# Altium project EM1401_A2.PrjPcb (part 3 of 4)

## Sheet uController.SchDoc: Microcontroller
size B; Date: Not shown in title block; ApprovedBy: Not shown in title block; CheckedBy: Not shown in title block; Author: Not shown in title block; CompanyName: Not shown in title block; DrawnBy: Not shown in title block; Engineer: Not shown in title block; Organization: Not shown in title block; Address1: Not shown in title block; Address2: Not shown in title block; Address3: Not shown in title block; Address4: Not shown in title block; DocumentNumber: 9; Revision: Use project parameter SCH_Rev; SheetNumber: 10; SheetTotal: 14; PageSetup: Record=PageOptions|CenterHorizontal=True|CenterVertical=True|PrintScale=1.09|XCorrection=1.00|YCorrection=1.00|PrintKind=0|BorderSize=5000000|LeftOffset=0|BottomOffset=0|Orientation=2|PaperLength=1000|PaperWidth=1000|Scale=100|PaperSource=15|PrintQuality=600|MediaType=1|DitherType=10|PaperKind=11x17|PrintScaleMode=1
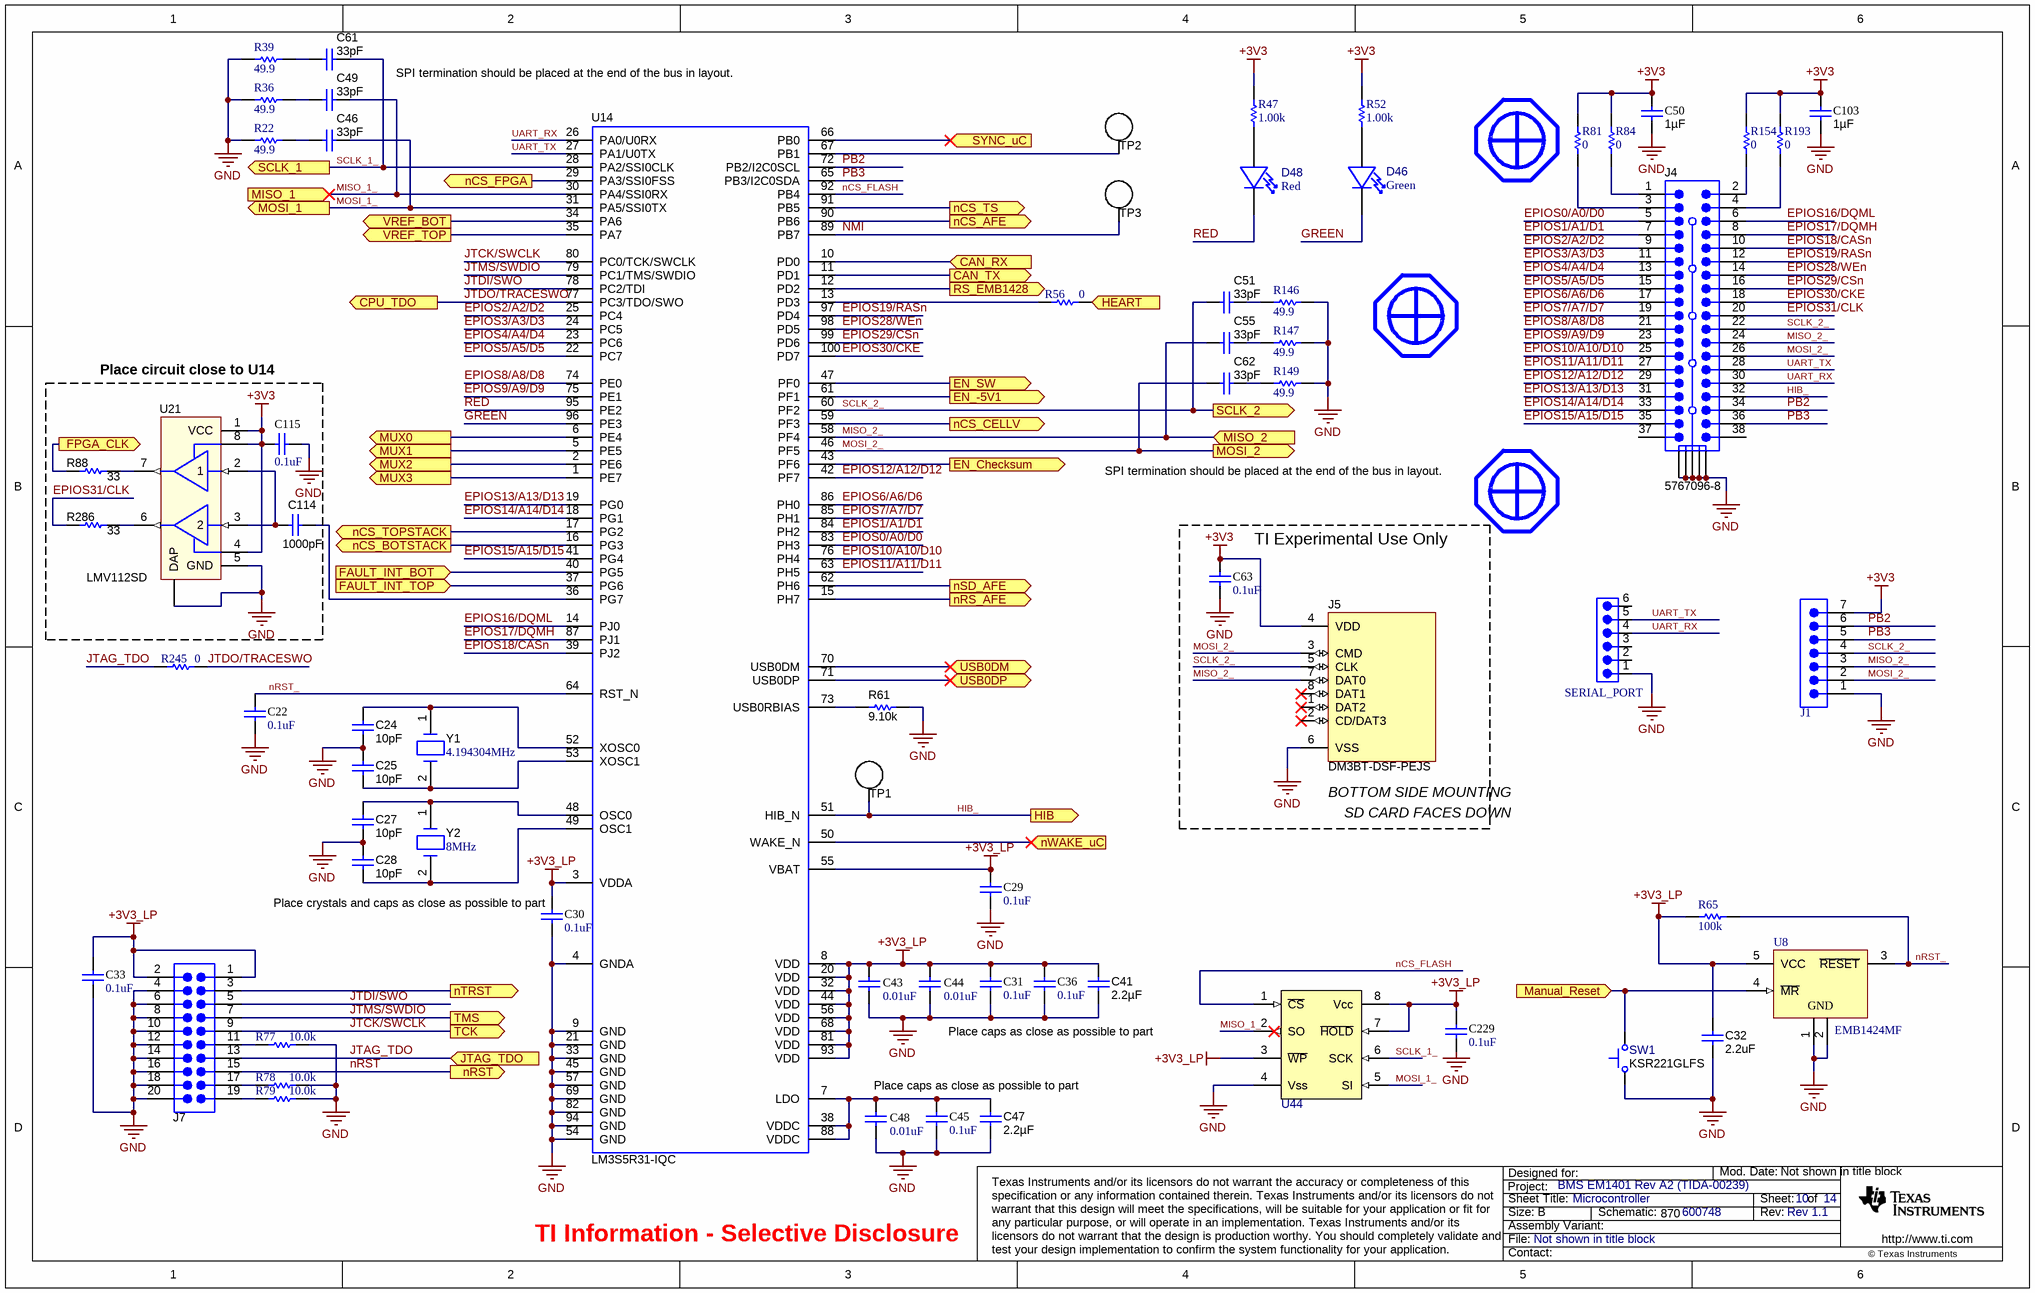
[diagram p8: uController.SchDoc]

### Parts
C22  value 0.1uF  [0603L]  (hidden comment: C1608X7R1C104K)
C24  ValueDisplayed: 10pF  [0603L]  (hidden comment: C1608C0G1H100D)
C25  ValueDisplayed: 10pF  [0603L]  (hidden comment: C1608C0G1H100D)
C27  ValueDisplayed: 10pF  [0603L]  (hidden comment: C1608C0G1H100D)
C28  ValueDisplayed: 10pF  [0603L]  (hidden comment: C1608C0G1H100D)
C29  value 0.1uF  [0603L]  (hidden comment: C1608X7R1C104K)
C30  value 0.1uF  [0603L]  (hidden comment: C1608X7R1C104K)
C31  value 0.1uF  [0603L]  (hidden comment: C1608X7R1C104K)
C32  value 2.2uF  [0805_HV]  (hidden comment: C2012X7R1C225K)
C33  value 0.1uF  [0603L]  (hidden comment: C1608X7R1C104K)
C36  value 0.1uF  [0603L]  (hidden comment: C1608X7R1C104K)
C41  ValueDisplayed: 2.2µF  [1210]  (hidden comment: GRM31MR71E225KA93L)
C43  value 0.01uF  [0603L]  (hidden comment: GRM188R71E103KA01D)
C44  value 0.01uF  [0603L]  (hidden comment: GRM188R71E103KA01D)
C45  value 0.1uF  [0603L]  (hidden comment: C1608X7R1C104K)
C46  value 33pF  [0603L]  (hidden comment: C1608C0G1H330J)
C47  ValueDisplayed: 2.2µF  [1210]  (hidden comment: GRM31MR71E225KA93L)
C48  value 0.01uF  [0603L]  (hidden comment: GRM188R71E103KA01D)
C49  value 33pF  [0603L]  (hidden comment: C1608C0G1H330J)
C50  ValueDisplayed: 1µF  [0603L]  (hidden comment: C1608X7R1C105K)
C51  value 33pF  [0603L]  (hidden comment: C1608C0G1H330J)
C55  value 33pF  [0603L]  (hidden comment: C1608C0G1H330J)
C61  value 33pF  [0603L]  (hidden comment: C1608C0G1H330J)
C62  value 33pF  [0603L]  (hidden comment: C1608C0G1H330J)
C63  value 0.1uF  [0603L]  (hidden comment: C1608X7R1C104K)
C103  ValueDisplayed: 1µF  [0603L]  (hidden comment: C1608X7R1C105K)
C114  ValueDisplayed: 1000pF  [0603L]  (hidden comment: GRM188R71C102KA01D)
C115  value 0.1uF  [0603L]  (hidden comment: C1608X7R1C104K)
C229  value 0.1uF  [0603L]  (hidden comment: C1608X7R1C104K)
D46  value Green  [HSMG-xxx]  (hidden comment: HSMG-C150)
D48  value Red  [HSMH-xxx]  (hidden comment: HSMH-C150)
J1  TSW-107-07-G-S  [TSW-107-XX-XXX-S]  (value not drawn)
J4  5767096-8
J5  DM3BT-DSF-PEJS  [DM3BT-DSF-PEJS]
J7  AWHW20-G-SMD-R  [2X10 Shrouded Surface Mount HDR]  (value not drawn)
MNT6  Used in BOM report  [4-40 screw]  (value not drawn)
MNT7  Used in BOM report  [4-40 screw]  (value not drawn)
MNT8  Used in BOM report  [4-40 screw]  (value not drawn)
R22  value 49.9  [0603L]  (hidden comment: CRCW060349R9FKEA)
R36  value 49.9  [0603L]  (hidden comment: CRCW060349R9FKEA)
R39  value 49.9  [0603L]  (hidden comment: CRCW060349R9FKEA)
R47  value 1.00k  [0603L]  (hidden comment: CRCW06031K00FKEA)
R52  value 1.00k  [0603L]  (hidden comment: CRCW06031K00FKEA)
R56  value 0  [0603L]  (hidden comment: CRCW06030000Z0EA)
R61  value 9.10k  [0603L]  (hidden comment: RC0603FR-079K1L)
R65  value 100k  [0603L]  (hidden comment: CRCW0603100KFKEA)
R77  value 10.0k  [0603L]  (hidden comment: CRCW060310K0FKEA)
R78  value 10.0k  [0603L]  (hidden comment: CRCW060310K0FKEA)
R79  value 10.0k  [0603L]  (hidden comment: CRCW060310K0FKEA)
R81  value 0  [0603L]  (hidden comment: CRCW06030000Z0EA)
R84  value 0  [0603L]  (hidden comment: CRCW06030000Z0EA)
R88  value 33  [0603L]  (hidden comment: CRCW060333R0JNEA)
R146  value 49.9  [0603L]  (hidden comment: CRCW060349R9FKEA)
R147  value 49.9  [0603L]  (hidden comment: CRCW060349R9FKEA)
R149  value 49.9  [0603L]  (hidden comment: CRCW060349R9FKEA)
R154  value 0  [0603L]  (hidden comment: CRCW06030000Z0EA)
R193  value 0  [0603L]  (hidden comment: CRCW06030000Z0EA)
R245  value 0  [0603L]  (hidden comment: CRCW06030000Z0EA)
R286  value 33  [0603L]  (hidden comment: CRCW060333R0JNEA)
SERIAL_PORT  961106-6404-AR  [1X6 100MIL PITCH]  (value not drawn)
SW1  KSR221GLFS  [KSR]
TP1  TESTPOINT  [TESTPOINT]  (value not drawn)  (no BOM)
TP2  TESTPOINT  [TESTPOINT]  (value not drawn)  (no BOM)
TP3  TESTPOINT  [TESTPOINT]  (value not drawn)  (no BOM)
U8  EMB1424MF  [MF05A_N]
U14  LM3S5R31-IQC  [QFP50P1600X1600X160-100N]
U21  LMV112SD  [SDA08A]
U44  25LC512T-I/SN  [M08A_L]  (value not drawn)
Y1  value 4.194304MHz  [HC-49US crystal]  (hidden comment: ABLSG-4.194304MHZ-D-2-Y-T)
Y2  value 8MHz  [HC-49US crystal]  (hidden comment: ABLS2-8.000MHZ-D4Y-T)

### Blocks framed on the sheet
Place circuit close to U14: C114 C115 R88 R286 U21
TI Experimental Use Only: C63 J5

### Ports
CAN_RX (in), CAN_TX (out), CPU_TDO (out), EN_-5V1 (out), EN_Checksum (out), EN_SW (out), FAULT_INT_BOT (in), FAULT_INT_TOP (in), FPGA_CLK (out), HEART (in), HIB (out), JTAG_TDO (in), Manual_Reset (in), MISO_1 (in), MISO_2 (in), MOSI_1 (out), MOSI_2 (out), MUX0 (out), MUX1 (out), MUX2 (out), MUX3 (out), nCS_AFE (out), nCS_BOTSTACK (out), nCS_CELLV (out), nCS_FPGA (out), nCS_TOPSTACK (out), nCS_TS (out), nRS_AFE (out), nRST (out), nSD_AFE (out), nTRST (out), nWAKE_uC (in), RS_EMB1428 (out), SCLK_1 (out), SCLK_2 (out), SYNC_uC (in), TCK (out), TMS (out), USB0DM (bidir), USB0DP (bidir), VREF_BOT (out), VREF_TOP (out)

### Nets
+3V3: C50.2 C63.1 C103.2 C115.2 J1.7 J5.4(VDD) R47.2 R52.2 R81.1 R84.1 R154.1 R193.1 U21.1(VCC) U21.4(EN2) U21.8(EN1)
+3V3_LP: C29.1 C30.1 C31.1 C32.1 C33.2 C36.1 C41.1 C43.2 C44.2 C229.2 J7.1 J7.2 R65.1 U8.5(VCC) U14.3(VDDA) U14.8(VDD) U14.20(VDD) U14.32(VDD) U14.44(VDD) U14.55(VBAT) U14.56(VDD) U14.68(VDD) U14.81(VDD) U14.93(VDD) U44.3(~{WP}) U44.7(~{HOLD}) U44.8(Vcc)
GND: C22.2 C24.2 C25.2 C27.2 C28.2 C29.2 C30.2 C31.2 C32.2 C33.1 C36.2 C41.2 C43.1 C44.1 C45.2 C47.2 C48.1 C50.1 C63.2 C103.1 C115.1 C229.1 J1.1 J4.39 J4.40 J4.41 J4.42 J4.43 J5.6(VSS) J7.4 J7.6 J7.8 J7.10 J7.12 J7.14 J7.16 J7.18 J7.20 R22.2 R36.2 R39.2 R61.2 R77.1 R78.1 R79.1 R146.1 R147.1 R149.1 SERIAL_PORT.1 SW1.1 U8.1(GND) U8.2(GND) U14.4(GNDA) U14.9(GND) U14.21(GND) U14.33(GND) U14.45(GND) U14.54(GND) U14.57(GND) U14.69(GND) U14.82(GND) U14.94(GND) U21.5(GND) U21.9(DAP) U44.4(Vss)  [project net BAT0]
EN_Checksum_: U14.43(PF6) ; port EN_Checksum
EN_SW_: U14.47(PF0) ; port EN_SW
EPIOS0/A0/D0: J4.5 U14.83(PH3)
EPIOS1/A1/D1: J4.7 U14.84(PH2)
EPIOS2/A2/D2: J4.9 U14.25(PC4)
EPIOS3/A3/D3: J4.11 U14.24(PC5)
EPIOS4/A4/D4: J4.13 U14.23(PC6)
EPIOS5/A5/D5: J4.15 U14.22(PC7)
EPIOS6/A6/D6: J4.17 U14.86(PH0)
EPIOS7/A7/D7: J4.19 U14.85(PH1)
EPIOS8/A8/D8: J4.21 U14.74(PE0)
EPIOS9/A9/D9: J4.23 U14.75(PE1)
EPIOS10/A10/D10: J4.25 U14.76(PH4)
EPIOS11/A11/D11: J4.27 U14.63(PH5)
EPIOS12/A12/D12: J4.29 U14.42(PF7)
EPIOS13/A13/D13: J4.31 U14.19(PG0)
EPIOS14/A14/D14: J4.33 U14.18(PG1)
EPIOS15/A15/D15: J4.35 U14.41(PG4)
EPIOS16/DQML: J4.6 U14.14(PJ0)
EPIOS17/DQMH: J4.8 U14.87(PJ1)
EPIOS18/CASn: J4.10 U14.39(PJ2)
EPIOS19/RASn: J4.12 U14.97(PD4)
EPIOS28/WEn: J4.14 U14.98(PD5)
EPIOS29/CSn: J4.16 U14.99(PD6)
EPIOS30/CKE: J4.18 U14.100(PD7)
EPIOS31/CLK: J4.20 R286.1
FAULT_INT_BOT_: U14.40(PG5) ; port FAULT_INT_BOT
FAULT_INT_TOP_: U14.37(PG6) ; port FAULT_INT_TOP
FPGA_CLK_: R88.1 ; port FPGA_CLK
GREEN: D46.2(Cathode) U14.96(PE3)
HEART_: R56.1 ; port HEART
HIB_: J4.32 TP1.1 U14.51(HIB_N) ; port HIB
JTAG_TDO: J7.13 R245.2 ; port JTAG_TDO
JTCK/SWCLK: J7.9 U14.80(PC0/TCK/SWCLK) ; port TCK
JTDI/SWO: J7.5 U14.78(PC2/TDI)
JTDO/TRACESWO: R245.1 U14.77(PC3/TDO/SWO) ; port CPU_TDO
JTMS/SWDIO: J7.7 U14.79(PC1/TMS/SWDIO) ; port TMS
Manual_Reset_: SW1.2 U8.4(~{MR}) ; port Manual_Reset
MISO_1_: C49.2 U14.30(PA4/SSI0RX) U44.2(SO) ; port MISO_1
MISO_2_: C55.1 J1.3 J4.24 J5.7(DAT0) U14.58(PF4) ; port MISO_2
MOSI_1_: C46.2 U14.31(PA5/SSI0TX) U44.5(SI) ; port MOSI_1
MOSI_2_: C62.1 J1.2 J4.26 J5.3(CMD) U14.46(PF5) ; port MOSI_2
MUX0_: U14.6(PE4) ; port MUX0
MUX1_: U14.5(PE5) ; port MUX1
MUX2_: U14.2(PE6) ; port MUX2
MUX3_: U14.1(PE7) ; port MUX3
nCS_AFE_: U14.90(PB6) ; port nCS_AFE
nCS_BOTSTACK_: U14.16(PG3) ; port nCS_BOTSTACK
nCS_CELLV_: U14.59(PF3) ; port nCS_CELLV
nCS_FLASH: U14.92(PB4) U44.1(~{CS})
nCS_FPGA_: U14.29(PA3/SSI0FSS) ; port nCS_FPGA
nCS_TOPSTACK_: U14.17(PG2) ; port nCS_TOPSTACK
nCS_TS_: U14.91(PB5) ; port nCS_TS
NMI: TP3.1 U14.89(PB7)
nRS_AFE_: U14.15(PH7) ; port nRS_AFE
nRST: J7.15 ; port nRST
nRST_: C22.1 R65.2 U8.3(~{RESET}) U14.64(RST_N)
nSD_AFE_: U14.62(PH6) ; port nSD_AFE
PB2: J1.6 J4.34 U14.72(PB2/I2C0SCL)
PB3: J1.5 J4.36 U14.65(PB3/I2C0SDA)
RED: D48.2(Cathode) U14.95(PE2)
RS_EMB1428_: U14.12(PD2) ; port RS_EMB1428
SCLK_1_: C61.2 U14.28(PA2/SSI0CLK) U44.6(SCK) ; port SCLK_1
SCLK_2_: C51.1 J1.4 J4.22 J5.5(CLK) U14.60(PF2) ; port SCLK_2
SYNC_: U14.66(PB0) ; port SYNC_uC
UART_RX: J4.30 SERIAL_PORT.4 U14.26(PA0/U0RX)
UART_TX: J4.28 SERIAL_PORT.5 U14.27(PA1/U0TX)
VREF_BOT_: U14.34(PA6) ; port VREF_BOT
VREF_TOP_: U14.35(PA7) ; port VREF_TOP
NetC24_1: C24.1 U14.52(XOSC0) Y1.1
NetC25_1: C25.1 U14.53(XOSC1) Y1.2
NetC27_1: C27.1 U14.48(OSC0) Y2.1
NetC28_1: C28.1 U14.49(OSC1) Y2.2
NetC45_1: C45.1 C47.1 C48.2 U14.7(LDO) U14.38(VDDC) U14.88(VDDC)
NetC46_1: C46.1 R22.1
NetC49_1: C49.1 R36.1
NetC51_2: C51.2 R146.2
NetC55_2: C55.2 R147.2
NetC61_1: C61.1 R39.1
NetC62_2: C62.2 R149.2
NetC114_1: C114.1 U14.36(PG7)
NetC114_2: C114.2 U21.2(IN1) U21.3(IN2)
NetD4_1: U14.70(USB0DM) ; port USB0DM
NetD9_1: U14.71(USB0DP) ; port USB0DP
NetD46_1: D46.1(Anode) R52.1
NetD48_1: D48.1(Anode) R47.1
NetJ4_1: J4.1 R84.2
NetJ4_2: J4.2 R154.2
NetJ4_3: J4.3 R81.2
NetJ4_4: J4.4 R193.2
NetJ7_3: J7.3 ; port nTRST
NetJ7_11: J7.11 R77.2
NetJ7_17: J7.17 R78.2
NetJ7_19: J7.19 R79.2
NetQ45_3: U14.50(WAKE_N) ; port nWAKE_uC
NetR27_1: U14.11(PD1) ; port CAN_TX
NetR38_1: U14.10(PD0) ; port CAN_RX
NetR56_2: R56.2 U14.13(PD3)
NetR61_1: R61.1 U14.73(USB0RBIAS)
NetR88_2: R88.2 U21.7(OUT1)
NetR94_2: U14.61(PF1) ; port EN_-5V1
NetR286_2: R286.2 U21.6(OUT2)
NetTP2_1: TP2.1 U14.67(PB1)

Not connected (* = marked no-connect by the designer): J4 37 38; J5 1(DAT2)* 2(CD/DAT3)* 8(DAT1)*; SERIAL_PORT 2 3 6

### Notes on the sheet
- SPI termination should be placed at the end of the bus in layout.
- (near MNT7) SPI termination should be placed at the end of the bus in layout.
- (near J5) BOTTOM SIDE MOUNTING
- SD CARD FACES DOWN
- (near C30) Place crystals and caps as close as possible to part
- Place caps as close as possible to part
- TI Information - Selective Disclosure

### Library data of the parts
C22 C29-C31 C33 C36 C45 C63 C115 C229 = C1608X7R1C104K: CAP, CERM, 0.1uF, 16V, +/-10%, X7R, 0603; Manufacturer: TDK; Cap_Case: 0603; ESR_Ohm: 0.017; Polarized: N; TaMax_C: 125; TaMin_C: -55; Tolerance_%: 10; VDC_V: 16; Cap_F: 0.0000001; CompType: Capacitor; Value1: 0.017 ohm; U/M: EA; ValueDisplayed: 0.1µF
C24 C25 C27 C28 = C1608C0G1H100D: CAP, CERM, 10pF, 50V, +/-5%, C0G/NP0, 0603; Manufacturer: TDK; Cap_Case: 0603; ESR_Ohm: 0.3492; Polarized: N; TaMax_C: 125; TaMin_C: -55; Tolerance_%: 5; VDC_V: 50; Cap_F: 0.00000000001; CompType: Capacitor; U/M: EA; Value1: 0.3492 ohm
C32 = C2012X7R1C225K: CAP, CERM, 2.2uF, 16V, +/-10%, X7R, 0805; Manufacturer: TDK; Cap_Case: 0805; ESR_Ohm: 0.0049; Polarized: N; TaMax_C: 125; TaMin_C: -55; Tolerance_%: 10; VDC_V: 16; Cap_F: 0.0000022; CompType: Capacitor; Value1: 0.0049 ohm; U/M: EA; ValueDisplayed: 2.2µF
C41 C47 = GRM31MR71E225KA93L: CAP, CERM, 2.2uF, 25V, +/-10%, X7R, 1206; Manufacturer: MuRata; Polarized: N; TaMax_C: 125; TaMin_C: -55; Tolerance_%: 10; VDC_V: 25; Cap_F: 0.0000022; CompType: Capacitor; U/M: EA
C43 C44 C48 = GRM188R71E103KA01D: CAP, CERM, 0.01uF, 25V, +/-10%, X7R, 0603; Manufacturer: MuRata; Cap_Case: 0603; Polarized: N; TaMax_C: 125; TaMin_C: -55; Tolerance_%: 10; VDC_V: 25; Cap_F: 0.00000001; CompType: Capacitor; U/M: EA; ValueDisplayed: 0.01µF
C46 C49 C51 C55 C61 C62 = C1608C0G1H330J: CAP, CERM, 33pF, 50V, +/-5%, C0G/NP0, 0603; Manufacturer: TDK; Cap_Case: 0603; ESR_Ohm: 0.2649; Polarized: N; TaMax_C: 125; TaMin_C: -55; Tolerance_%: 5; VDC_V: 50; Cap_F: 0.000000000033; CompType: Capacitor; Value1: 0.2649 ohm; U/M: EA
C50 C103 = C1608X7R1C105K: CAP, CERM, 1uF, 16V, +/-10%, X7R, 0603; Manufacturer: TDK; Cap_Case: 0603; ESR_Ohm: 0.0057; Polarized: N; TaMax_C: 125; TaMin_C: -55; Tolerance_%: 10; VDC_V: 16; Cap_F: 0.000001; CompType: Capacitor; Value1: 0.0057 ohm; U/M: EA
C114 = GRM188R71C102KA01D: CAP, CERM, 1000pF, 16V, +/-10%, X7R, 0603; Manufacturer: MuRata; Polarized: N; CompType: Capacitor; U/M: EA; Cap_F: 0.000000001; Tolerance_%: 10; VDC_V: 16; TaMin_C: -55; TaMax_C: 125; Cap_Case: 0603
D46 = HSMG-C150: LED 570NM GREEN DIFF 1206 SMD; Manufacturer: Avago Technologies; SymbolVersion: 06-2009; SymbolCreator: Use LDAP id
D48 = HSMH-C150: LED 660NM RED DIFF 1206 SMD; Manufacturer: Avago Technologies; SymbolVersion: 06-2009; SymbolCreator: Use LDAP id
J1 = TSW-107-07-G-S: Header, TH, 100mil, 7x1, Gold plated, 230 mil above insulator; Manufacturer: Samtec, Inc.; U/M: EA
J4 = 5767096-8 (Mictor 38): Mictor Receptacle, SMD 25mil, 19x2, Gold plated, 236 mil above insulator; Manufacturer: Tyco Electronics; U/M: EA
J5 = DM3BT-DSF-PEJS: CONN MICRO SD R/A PUSH-PUSH SMD; Manufacturer: Hirose; SymbolVersion: use current date i.e. 2008-05-20; SymbolCreator: Use LDAP id; CompType: Card Connector
J7 = AWHW20-G-SMD-R: GREY CONN SHROUDED 2x10 HEADER SMT 100mil pitch; Manufacturer: Assman Electronics; CompType: Connector
MNT6-MNT8 = 4-40 screw mount: 4-40 screw for mounting hardware; SymbolVersion: use current date i.e. 2008-05-20; SymbolCreator: Use LDAP id
R22 R36 R39 R146 R147 R149 = CRCW060349R9FKEA: RES, 49.9 ohm, 1%, 0.1W, 0603; Manufacturer: Vishay-Dale; CompType: Resistor; Tolerance_%: 1; VDC_V: 75; Power_W: 0.1; Value_Code: 49R9; EIA_Code: E96; TempCo: 100 ppm/C; U/M: EA
R47 R52 = CRCW06031K00FKEA: RES, 1.00k ohm, 1%, 0.1W, 0603; Manufacturer: Vishay-Dale; CompType: Resistor; Tolerance_%: 1; VDC_V: 75; Power_W: 0.1; Res_Ohm: 1000; Value_Code: 1k00; EIA_Code: E96; TempCo: 100 ppm/C; U/M: EA
R56 R81 R84 R154 R193 R245 = CRCW06030000Z0EA: RES, 0 ohm, 5%, 0.1W, 0603; Manufacturer: Vishay-Dale; CompType: Resistor; Tolerance_%: 5; VDC_V: 75; Power_W: 0.1; Value_Code: 0000; EIA_Code: E24; TempCo: 200 ppm/C; U/M: EA
R61 = RC0603FR-079K1L: RES, 9.10k ohm, 1%, 0.1W, 0603; Manufacturer: Yageo America; CompType: Resistor; Tolerance_%: 1; VDC_V: 150; Power_W: 0.1; Res_ohm: 9100; Value_Code: 9k10; U/M: EA; TempCo: 200 ppm/C
R65 = CRCW0603100kFKEA: RES, 100k ohm, 1%, 0.1W, 0603; Manufacturer: Vishay-Dale; CompType: Resistor; Tolerance_%: 1; VDC_V: 75; Power_W: 0.1; Res_Ohm: 100000; EIA_Code: E96; TempCo: 100 ppm/C; U/M: EA
R77-R79 = CRCW060310k0FKEA: RES, 10.0k ohm, 1%, 0.1W, 0603; Manufacturer: Vishay-Dale; CompType: Resistor; Tolerance_%: 1; VDC_V: 75; Power_W: 0.1; Res_Ohm: 10000; Value_Code: 10k0; EIA_Code: E96; TempCo: 100 ppm/C; U/M: EA
R88 R286 = CRCW060333R0JNEA: RES, 33 ohm, 5%, 0.1W, 0603; Manufacturer: Vishay-Dale; CompType: Resistor; Value_Code: 33R0; Tolerance_%: 5; Power_W: 0.1; VDC_V: 75; TempCo: 200 ppm/C; EIA_Code: E24; U/M: EA
SERIAL_PORT = 961106-6404-AR: CONN 1X6 HEADER 100mil pitch; Manufacturer: 3M; CompType: Connector; I max: 2A
SW1 = KSR221GLFS: Switch, Normally open, 2.3N force, 200k operations, SMD; Manufacturer: C and K Components; CompType: SPST Switch; U/M: EA
TP1-TP3 = TESTPOINT: TEST POINT.  No entry in BOM.; PartNumber: Used in BOM report
U8 = EMB1424MF: 5-Pin Microprocessor Reset Circuits; Manufacturer: National Semiconductor; CompType: MiscPower; PowerWise: N
U14 = LM3S5R31-IQC: Stellaris ARM Cortex-M3 Microcontroller; PartNumber: LM3S5R31-IQC-C5; Manufacturer: Texas Instruments; Stellaris Class: Tempest
U21 = LMV112SD: 40MHz Dual Clock Buffer; Manufacturer: National Semiconductor; Characteristics: LMV112 40MHz Dual Clock Buffer; CompType: Buffer IC; TaMin_C: -40.0; TaMax_C: 85.0
U44 = 25LC512: IC EEPROM 512KBIT 20MHZ; Manufacturer: Micorchip Technology; SymbolVersion: use current date i.e. 2008-05-20; SymbolCreator: Use LDAP id
Y1 = HC/49US - 4.194304MHz: SMD Low Profile Crystal; Manufacturer: Abracon Corporation; CompType: Oscillator; Drive Level: 1mW; Value1: 18pf
Y2 = HC/49US - 8MHz: SMD Low Profile Crystal; Manufacturer: Abracon Corporation; CompType: Oscillator; Drive Level: 1mW; Value1: 18pf

## Sheet Communications.SchDoc: Communications
size B; Date: Not shown in title block; ApprovedBy: Not shown in title block; CheckedBy: Not shown in title block; Author: Not shown in title block; CompanyName: Not shown in title block; DrawnBy: Not shown in title block; Engineer: Not shown in title block; Organization: Not shown in title block; Address1: Not shown in title block; Address2: Not shown in title block; Address3: Not shown in title block; Address4: Not shown in title block; DocumentNumber: 10; Revision: Use project parameter SCH_Rev; SheetNumber: 11; SheetTotal: 14; PageSetup: Record=PageOptions|CenterHorizontal=True|CenterVertical=True|PrintScale=0.75|XCorrection=1.00|YCorrection=1.00|PrintKind=0|BorderSize=5000000|LeftOffset=0|BottomOffset=0|Orientation=2|PaperLength=1000|PaperWidth=1000|Scale=100|PaperSource=15|PrintQuality=600|MediaType=1|DitherType=10|PaperKind=A4|PrintScaleMode=1
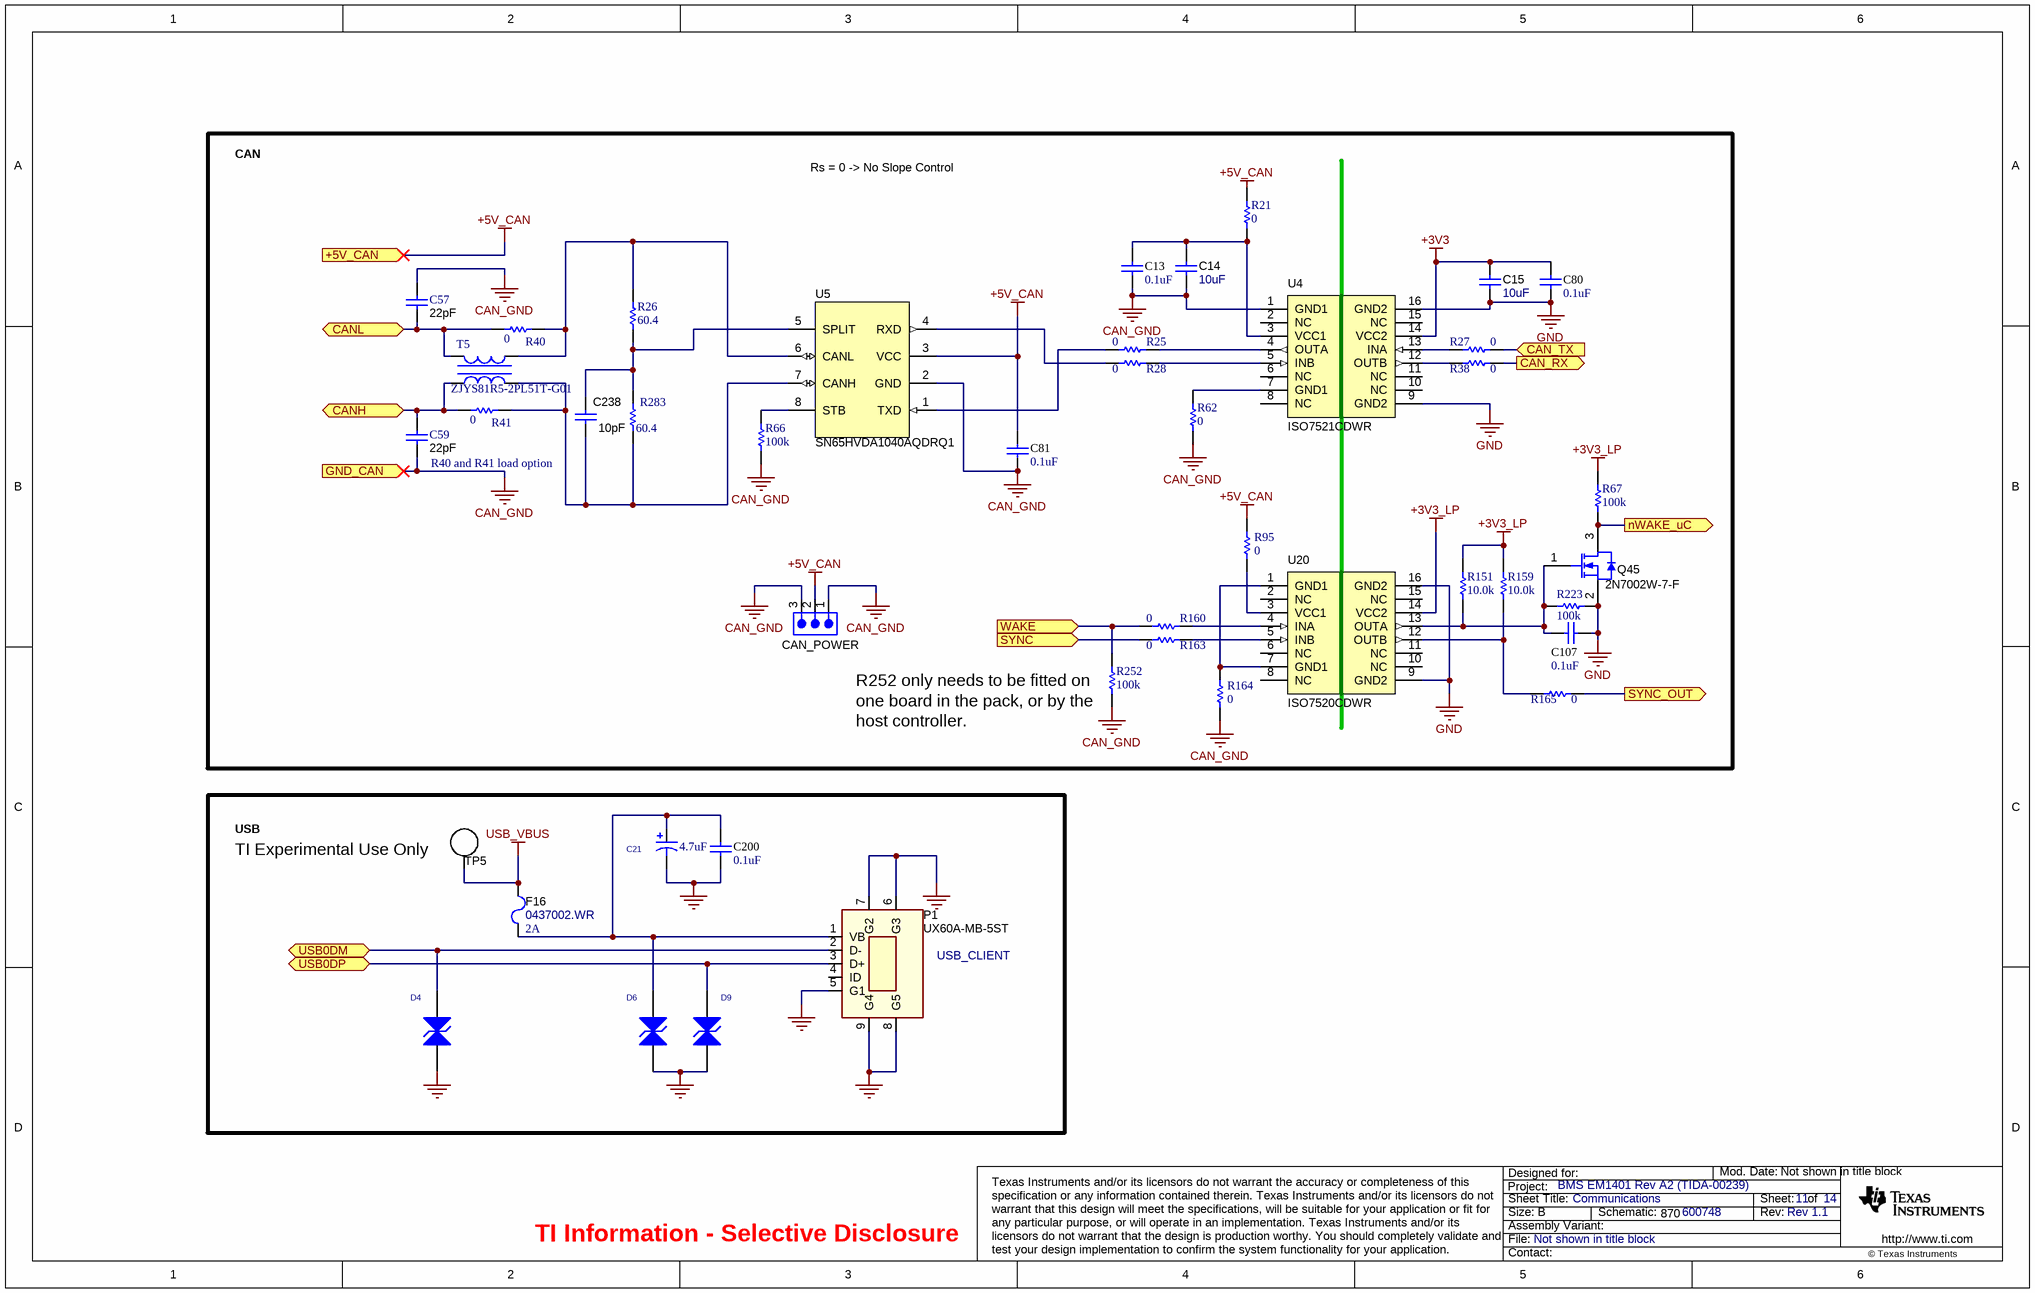
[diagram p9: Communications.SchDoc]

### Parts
C13  value 0.1uF  [0603L]  (hidden comment: 0603YC104JAT2A)
C14  value 10uF  [1206L]  (hidden comment: C3216X7R1C106M)
C15  value 10uF  [1206L]  (hidden comment: C3216X7R1C106M)
C21  value 4.7uF  [6032-28]  (hidden comment: TPSC475K035R0600)
C57  ValueDisplayed: 22pF  [0603L]  (hidden comment: 06035A220JAT2A)
C59  ValueDisplayed: 22pF  [0603L]  (hidden comment: 06035A220JAT2A)
C80  value 0.1uF  [0603L]  (hidden comment: 0603YC104JAT2A)
C81  value 0.1uF  [0603L]  (hidden comment: C1608X7R1C104K)
C107  value 0.1uF  [0603L]  (hidden comment: C1608X7R1C104K)
C200  value 0.1uF  [0603L]  (hidden comment: C1608X7R1C104K)
C238  value 10pF  [0603L]  (hidden comment: C0603C100J5GACTU)
CAN_POWER  961103-6404-AR  [1X3 100MIL PITCH]  (value not drawn)
D4  Used in BOM report  [0603L]  (value not drawn)
D6  Used in BOM report  [0603L]  (value not drawn)
D9  Used in BOM report  [0603L]  (value not drawn)
F16  0437002.WR  value 2A  [1206M]
P1  UX60A-MB-5ST  [UX60A-MB-5ST]
Q45  2N7002W-7-F  [SOT-323]
R21  value 0  [0603L]  (hidden comment: CRCW06030000Z0EA)
R25  value 0  [0603L]  (hidden comment: CRCW06030000Z0EA)
R26  value 60.4  [0603L]  (hidden comment: CRCW060360R4FKEA)
R27  value 0  [0603L]  (hidden comment: CRCW06030000Z0EA)
R28  value 0  [0603L]  (hidden comment: CRCW06030000Z0EA)
R38  value 0  [0603L]  (hidden comment: CRCW06030000Z0EA)
R40  value 0  [0603L]  (hidden comment: CRCW06030000Z0EA)
R41  value 0  [0603L]  (hidden comment: CRCW06030000Z0EA)
R62  value 0  [0603L]  (hidden comment: CRCW06030000Z0EA)
R66  value 100k  [0603L]  (hidden comment: RT0603DRE07100KL)
R67  value 100k  [0603L]  (hidden comment: RT0603DRE07100KL)
R95  value 0  [0603L]  (hidden comment: CRCW06030000Z0EA)
R151  value 10.0k  [0603L]  (hidden comment: CRCW060310K0FKEA)
R159  value 10.0k  [0603L]  (hidden comment: CRCW060310K0FKEA)
R160  value 0  [0603L]  (hidden comment: CRCW06030000Z0EA)
R163  value 0  [0603L]  (hidden comment: CRCW06030000Z0EA)
R164  value 0  [0603L]  (hidden comment: CRCW06030000Z0EA)
R165  value 0  [0603L]  (hidden comment: CRCW06030000Z0EA)
R223  value 100k  [0603L]  (hidden comment: RT0603DRE07100KL)
R252  value 100k  [0603L]  (hidden comment: RT0603DRE07100KL)
R283  value 60.4  [0603L]  (hidden comment: CRCW060360R4FKEA)
T5  ZJYS81R5-2PL51T-G01  [TDK Choke]
TP5  TESTPOINT  [TESTPOINT]  (value not drawn)  (no BOM)
U4  ISO7521CDWR  [SOIC16 Wide]
U5  SN65HVDA1040AQDRQ1  [M08A_M]
U20  ISO7520CDWR  [SOIC16 Wide]

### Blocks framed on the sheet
TI Experimental Use Only: C21 C200 D4 D6 D9 F16 P1 TP5

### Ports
+5V_CAN (in), CAN_RX (out), CAN_TX (in), CANH (bidir), CANL (bidir), GND_CAN (in), nWAKE_uC (out), SYNC (in), SYNC_OUT (out), USB0DM (bidir), USB0DP (bidir), WAKE (in)

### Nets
+3V3: C15.2 C80.2 U4.14(VCC2)
+3V3_LP: R67.1 R151.1 R159.1 U20.14(VCC2)
+5V_CAN: C81.2 CAN_POWER.2 R21.1 R95.2 U5.3(VCC) ; port +5V_CAN
CAN_GND: C13.1 C14.1 C57.1 C59.2 C81.1 CAN_POWER.1 CAN_POWER.3 R62.2 R66.2 R164.1 R252.2 U4.1(GND1) U5.2(GND) ; port GND_CAN
GND: C15.1 C21.2(-) C80.1 C107.1 C200.1 D4.2(K) D6.2(K) D9.2(K) P1.5(G1) P1.6(G3) P1.7(G2) P1.8(G5) P1.9(G4) Q45.2(S) R223.2 U4.9(GND2) U4.16(GND2) U20.9(GND2) U20.16(GND2)  [project net BAT0]
USB_VBUS: F16.2 TP5.1
SYNC_: R165.1 ; port SYNC_OUT
NetC13_2: C13.2 C14.2 R21.2 U4.3(VCC1)
NetC21_1: C21.1(+) C200.2 D6.1(A) F16.1 P1.1(VB)
NetC57_2: C57.2 R40.2 T5.1 ; port CANL
NetC59_1: C59.1 R41.2 T5.2 ; port CANH
NetC107_2: C107.2 Q45.1(G) R151.2 R223.1 U20.13(OUTA)
NetC238_1: C238.1 R26.1 R283.2 U5.5(SPLIT)
NetC238_2: C238.2 R41.1 R283.1 T5.3 U5.7(CANH)
NetD4_1: D4.1(A) P1.2(D-) ; port USB0DM
NetD9_1: D9.1(A) P1.3(D+) ; port USB0DP
NetP3_A4: R163.2 ; port SYNC
NetP3_A5: R160.2 R252.1 ; port WAKE
NetQ45_3: Q45.3(D) R67.2 ; port nWAKE_uC
NetR25_1: R25.1 U4.4(OUTA)
NetR25_2: R25.2 U5.1(TXD)
NetR26_2: R26.2 R40.1 T5.4 U5.6(CANL)
NetR27_1: R27.1 ; port CAN_TX
NetR27_2: R27.2 U4.13(INA)
NetR28_1: R28.1 U4.5(INB)
NetR28_2: R28.2 U5.4(RXD)
NetR38_1: R38.1 ; port CAN_RX
NetR38_2: R38.2 U4.12(OUTB)
NetR62_1: R62.1 U4.7(GND1)
NetR66_1: R66.1 U5.8(STB)
NetR95_1: R95.1 U20.3(VCC1)
NetR159_2: R159.2 R165.2 U20.12(OUTB)
NetR160_1: R160.1 U20.4(INA)
NetR163_1: R163.1 U20.5(INB)
NetR164_2: R164.2 U20.1(GND1) U20.7(GND1)

Not connected (* = marked no-connect by the designer): P1 4(ID); U4 2(NC) 6(NC) 8(NC) 10(NC) 11(NC) 15(NC); U20 2(NC) 6(NC) 8(NC) 10(NC) 11(NC) 15(NC)

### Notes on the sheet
- CAN
- Rs = 0 -> No Slope Control
- (near C59) R40 and R41 load option
- (near R252) R252 only needs to be fitted on
- (near R252) one board in the pack, or by the
- host controller.
- USB
- (near P1) USB_CLIENT
- TI Information - Selective Disclosure

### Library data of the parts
C13 C80 = 0603YC104JAT2A: CAP, CERM, 0.1uF, 16V, +/-5%, X7R, 0603; Manufacturer: AVX; Cap_Case: 0603; ESR_Ohm: 0.039; Polarized: N; TaMax_C: 125; TaMin_C: -55; Tolerance_%: 5; VDC_V: 16; Cap_F: 0.0000001; CompType: Capacitor; Value1: 0.039 ohm; U/M: EA; ValueDisplayed: 0.1µF
C14 C15 = C3216X7R1C106M: CAP, CERM, 10uF, 16V, +/-20%, X7R, 1206; Manufacturer: TDK; Cap_Case: 1206; ESR_Ohm: 0.0046; Polarized: N; TaMax_C: 125; TaMin_C: -55; Tolerance_%: 20; VDC_V: 16; Cap_F: 0.00001; CompType: Capacitor; Value1: 0.0046 ohm; U/M: EA; ValueDisplayed: 10µF
C21 = TPSC475K035R0600: TA, 35V, 10%, 0.6Ohm ESR; Manufacturer: AVX; CompType: Capacitor; Cap_Case: C; ESR_Ohm: 0.6; IRMS_A: 0.385; Polarized: Y; TaMax_C: 125; TaMin_C: -55; Tolerance_%: 10; VDC_V: 35; Cap_F: 4.7E-6; Dielectric: TPS
C57 C59 = 06035A220JAT2A: CAP, CERM, 22pF, 50V, +/-5%, C0G/NP0, 0603; Manufacturer: AVX; Cap_Case: 0603; ESR_Ohm: 0.259; Polarized: N; TaMax_C: 125; TaMin_C: -55; Tolerance_%: 5; VDC_V: 50; Cap_F: 0.000000000022; CompType: Capacitor; Value1: 0.259 ohm; U/M: EA
C81 C107 C200 = C1608X7R1C104K: as C22 on sheet uController
C238 = C0603C100J5GACTU: CAP, CERM, 10pF, 50V, +/-5%, C0G/NP0, 0603; Manufacturer: Kemet; Cap_Case: 0603; Polarized: N; TaMax_C: 125; TaMin_C: -55; Tolerance_%: 5; VDC_V: 50; Cap_F: 0.00000000001; CompType: Capacitor; U/M: EA
CAN_POWER = 961103-6404-AR: CONN 1X3 HEADER 100mil pitch; Manufacturer: 3M; CompType: Connector; I max: 2A
D4 D6 D9 = TVS_Diode: TVS Diode, xxxW, xxV, xx%, [PackageReference]; CompType: Transorb; U/M: EA
F16 = 0437002.WR: FUSE 2A 63V  FAST ACTING; Manufacturer: LittleFuse Inc; SymbolVersion: use current date i.e. 2008-05-20; SymbolCreator: Use LDAP id
P1 = UX60A-MB-5ST: CONN RECEPT MINI USB2.0 5POS; Manufacturer: Hirose; SymbolVersion: use current date i.e. 2008-05-20; SymbolCreator: Use LDAP id; CompType: Connector
Q45 = 2N7002W-7-F: MOSFET N-CH 60V 115MA SOT323; Manufacturer: Vishay-Siliconix; ChType: N; VdsMax_V: 60; Value1: 1.8 ohm; Rdson45_Ohm: 1.8; Value2: 0.4 nC; QgTyp_nC: 0.4; Vgs_V: 20; IdsMax_A: 0.24
R21 R25 R27 R28 R38 R40 R41 R62 R95 R160 R163-R165 = CRCW06030000Z0EA: as R56 on sheet uController
R26 R283 = CRCW060360R4FKEA: RES, 60.4 ohm, 1%, 0.1W, 0603; Manufacturer: Vishay-Dale; CompType: Resistor; Tolerance_%: 1; VDC_V: 75; Power_W: 0.1; Value_Code: 60R4; EIA_Code: E96; TempCo: 100 ppm/C; U/M: EA
R66 R67 R223 R252 = RT0603DRE07100KL: 0.5%, 0.1W; Manufacturer: Yageo America; CompType: Resistor; Tolerance_%: 0.5; VDC_V: 75; Power_W: 0.1; Res_Ohm: 100000; EIA_Code: E192
R151 R159 = CRCW060310K0FKEA: RES, 10.0k ohm, 1%, 0.1W, 0603; Manufacturer: Vishay-Dale; CompType: Resistor; Tolerance_%: 1; VDC_V: 75; Power_W: 0.1; Res_Ohm: 10000; Value_Code: 10k0; EIA_Code: E96; TempCo: 100 ppm/C; U/M: EA
T5 = ZJYS81R5-2PL51T-G01: CHOKE COMM MODE 1000 OHM .5A SMD; Manufacturer: TDK; CompType: Common Mode Choke
TP5 = TESTPOINT: as TP1 on sheet uController
U4 = ISO7251: Low Power 3-Channel Digital Isolator; Manufacturer: TI
U5 = SN65HVDA1040A: CAN transceiver; Manufacturer: TI; DesignatorOriginal: U5_MOD5; A_Properties: IC CAN TRANSCEIVER 5V HS 8-SOIC; Val_4: HS; Val_3: 5V; Val_5: SO-8
U20 = ISO7250: Low Power 3-Channel Digital Isolator; Manufacturer: TI

## Sheet Battery Stack Protection.SchDoc: Battery Stack Protection
size C; Date: Not shown in title block; ApprovedBy: Not shown in title block; CheckedBy: Not shown in title block; Author: Not shown in title block; CompanyName: Not shown in title block; DrawnBy: Not shown in title block; Engineer: Not shown in title block; Organization: Not shown in title block; Address1: Not shown in title block; Address2: Not shown in title block; Address3: Not shown in title block; Address4: Not shown in title block; DocumentNumber: 1; Revision: Use project parameter SCH_Rev; SheetNumber: 4; SheetTotal: 14; PageSetup: Record=PageOptions|CenterHorizontal=True|CenterVertical=True|PrintScale=0.54|XCorrection=1.00|YCorrection=1.00|PrintKind=0|BorderSize=5000000|LeftOffset=0|BottomOffset=0|Orientation=2|PaperLength=1000|PaperWidth=1000|Scale=100|PaperSource=15|PrintQuality=600|MediaType=1|DitherType=10|PaperKind=Letter|PrintScaleMode=1
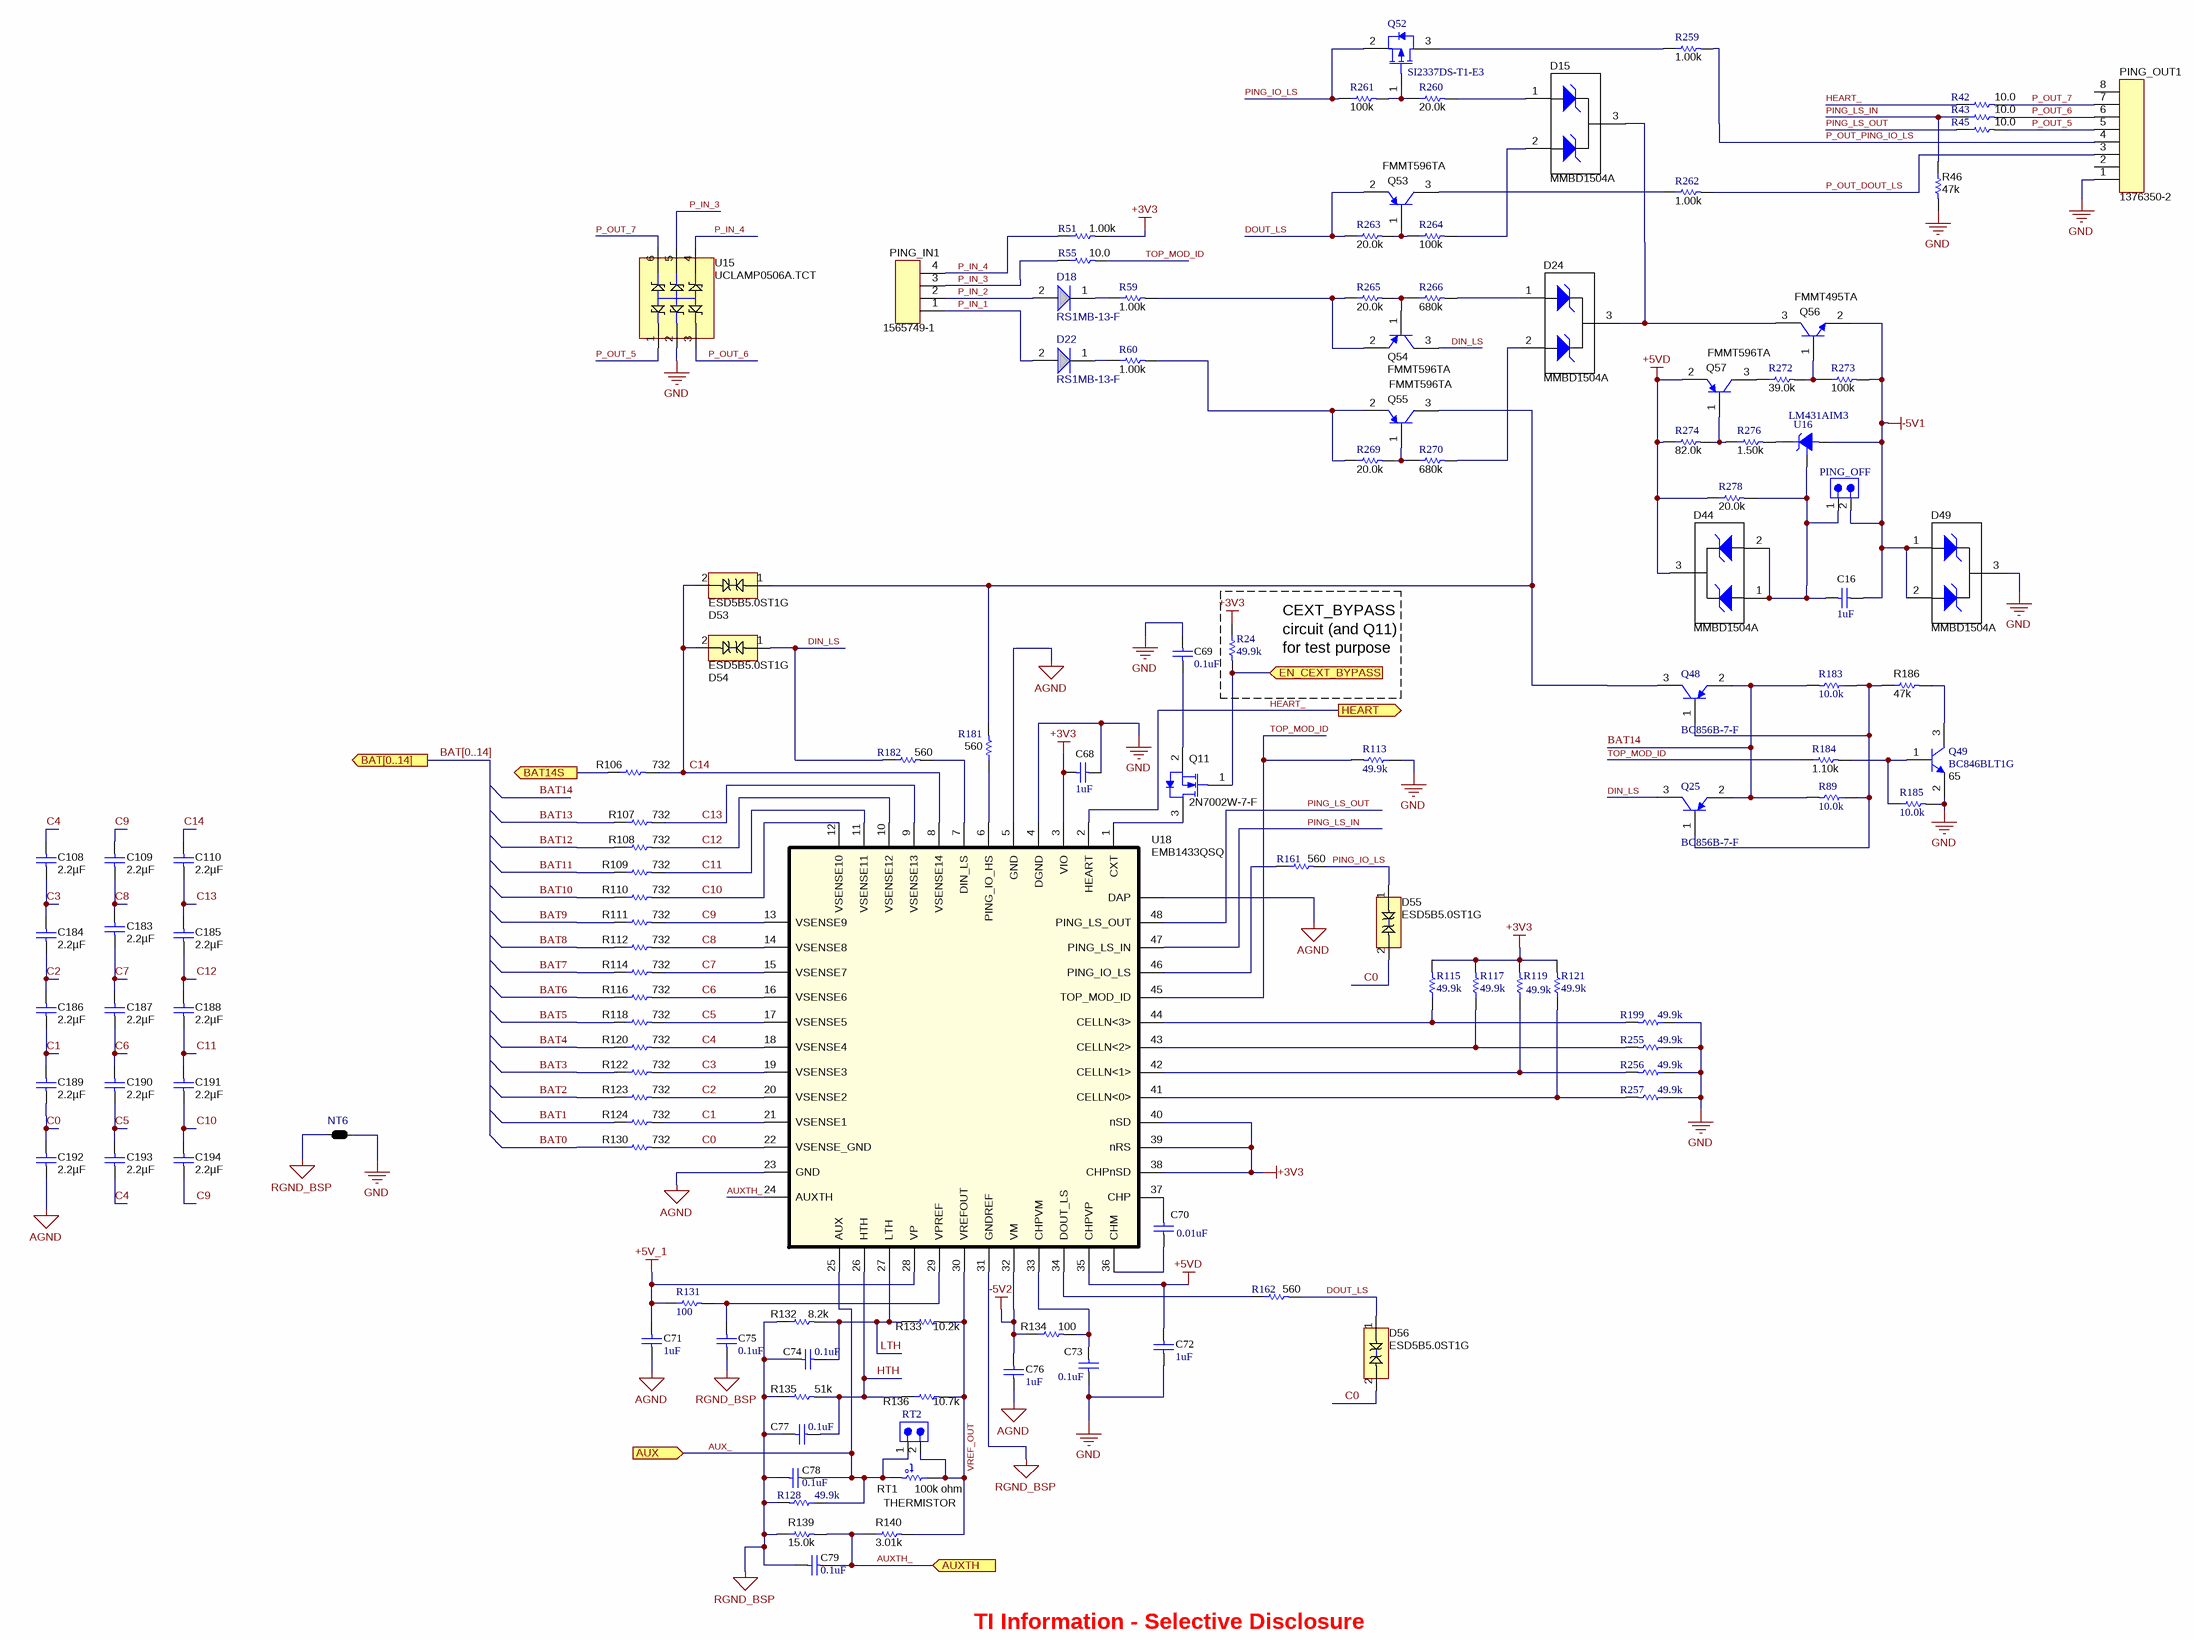
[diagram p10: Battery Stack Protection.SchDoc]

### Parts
C16  value 1uF  [0805_HV]  (hidden comment: C2012X7R1E105K)
C68  value 1uF  [0805_HV]  (hidden comment: C2012X7R1E105K)
C69  value 0.1uF  [0603L]  (hidden comment: C1608X7R1C104K)
C70  value 0.01uF  [0603L]  (hidden comment: C1608X7R1H103K)
C71  value 1uF  [0805_HV]  (hidden comment: C2012X7R1E105K)
C72  value 1uF  [0805_HV]  (hidden comment: C2012X7R1E105K)
C73  value 0.1uF  [0603L]  (hidden comment: C1608X7R1C104K)
C74  value 0.1uF  [0603L]  (hidden comment: C1608X7R1C104K)
C75  value 0.1uF  [0603L]  (hidden comment: C1608X7R1C104K)
C76  value 1uF  [0805_HV]  (hidden comment: C2012X7R1E105K)
C77  value 0.1uF  [0603L]  (hidden comment: C1608X7R1C104K)
C78  value 0.1uF  [0603L]  (hidden comment: C1608X7R1C104K)
C79  value 0.1uF  [0603L]  (hidden comment: C1608X7R1C104K)
C108  ValueDisplayed: 2.2µF  [0603L]  (hidden comment: C0603C225K9PACTU)
C109  ValueDisplayed: 2.2µF  [0603L]  (hidden comment: C0603C225K9PACTU)
C110  ValueDisplayed: 2.2µF  [0603L]  (hidden comment: C0603C225K9PACTU)
C183  ValueDisplayed: 2.2µF  [0603L]  (hidden comment: C0603C225K9PACTU)
C184  ValueDisplayed: 2.2µF  [0603L]  (hidden comment: C0603C225K9PACTU)
C185  ValueDisplayed: 2.2µF  [0603L]  (hidden comment: C0603C225K9PACTU)
C186  ValueDisplayed: 2.2µF  [0603L]  (hidden comment: C0603C225K9PACTU)
C187  ValueDisplayed: 2.2µF  [0603L]  (hidden comment: C0603C225K9PACTU)
C188  ValueDisplayed: 2.2µF  [0603L]  (hidden comment: C0603C225K9PACTU)
C189  ValueDisplayed: 2.2µF  [0603L]  (hidden comment: C0603C225K9PACTU)
C190  ValueDisplayed: 2.2µF  [0603L]  (hidden comment: C0603C225K9PACTU)
C191  ValueDisplayed: 2.2µF  [0603L]  (hidden comment: C0603C225K9PACTU)
C192  ValueDisplayed: 2.2µF  [0603L]  (hidden comment: C0603C225K9PACTU)
C193  ValueDisplayed: 2.2µF  [0603L]  (hidden comment: C0603C225K9PACTU)
C194  ValueDisplayed: 2.2µF  [0603L]  (hidden comment: C0603C225K9PACTU)
D15  MMBD1504A  [MF03A_L]
D18  RS1MB-13-F  [SMB]
D22  RS1MB-13-F  [SMB]
D24  MMBD1504A  [MF03A_L]
D44  MMBD1504A  [MF03A_L]
D49  MMBD1504A  [MF03A_L]
D53  ESD5B5.0ST1G  [SOD523 TVS]
D54  ESD5B5.0ST1G  [SOD523 TVS]
D55  ESD5B5.0ST1G  [SOD523 TVS]
D56  ESD5B5.0ST1G  [SOD523 TVS]
NT6  (no value)  [0805_Net_Tie]  (net tie, no BOM)
PING_IN1  1565749-1  [1565749-1]
PING_OFF  961102-6404-AR  [1X2 100MIL PITCH]  (value not drawn)
PING_OUT1  1376350-2  [1376350-2]
Q11  2N7002W-7-F  [SOT-323]
Q25  BC856B-7-F  [SOT-23]
Q48  BC856B-7-F  [SOT-23]
Q49  BC846BLT1G  Vceo_V: 65  [SOT-23]
Q52  SI2337DS-T1-E3  [SOT-23]
Q53  FMMT596TA  [SOT-23]
Q54  FMMT596TA  [SOT-23]
Q55  FMMT596TA  [SOT-23]
Q56  FMMT495TA  [SOT-23]
Q57  FMMT596TA  [SOT-23]
R24  value 49.9k  [0603L]  (hidden comment: CRCW060349K9FKEA)
R42  value 10.0  [0603L]  (hidden comment: RC0603FR-0710RL)
R43  value 10.0  [0603L]  (hidden comment: RC0603FR-0710RL)
R45  value 10.0  [0603L]  (hidden comment: RC0603FR-0710RL)
R46  value 47k  [0603L]  (hidden comment: CRCW060347K0JNEA)
R51  value 1.00k  [0603L]  (hidden comment: CRCW06031K00FKEA)
R55  value 10.0  [0603L]  (hidden comment: RC0603FR-0710RL)
R59  value 1.00k  [0603L]  (hidden comment: CRCW06031K00FKEA)
R60  value 1.00k  [0603L]  (hidden comment: CRCW06031K00FKEA)
R89  value 10.0k  [0603L]  (hidden comment: CRCW060310K0FKEA)
R106  value 732  [0603L]  (hidden comment: CRCW0603732RFKEA)
R107  value 732  [0603L]  (hidden comment: CRCW0603732RFKEA)
R108  value 732  [0603L]  (hidden comment: CRCW0603732RFKEA)
R109  value 732  [0603L]  (hidden comment: CRCW0603732RFKEA)
R110  value 732  [0603L]  (hidden comment: CRCW0603732RFKEA)
R111  value 732  [0603L]  (hidden comment: CRCW0603732RFKEA)
R112  value 732  [0603L]  (hidden comment: CRCW0603732RFKEA)
R113  value 49.9k  [0603L]  (hidden comment: CRCW060349K9FKEA)
R114  value 732  [0603L]  (hidden comment: CRCW0603732RFKEA)
R115  value 49.9k  [0603L]  (hidden comment: CRCW060349K9FKEA)
R116  value 732  [0603L]  (hidden comment: CRCW0603732RFKEA)
R117  value 49.9k  [0603L]  (hidden comment: CRCW060349K9FKEA)
R118  value 732  [0603L]  (hidden comment: CRCW0603732RFKEA)
R119  value 49.9k  [0603L]  (hidden comment: CRCW060349K9FKEA)
R120  value 732  [0603L]  (hidden comment: CRCW0603732RFKEA)
R121  value 49.9k  [0603L]  (hidden comment: CRCW060349K9FKEA)
R122  value 732  [0603L]  (hidden comment: CRCW0603732RFKEA)
R123  value 732  [0603L]  (hidden comment: CRCW0603732RFKEA)
R124  value 732  [0603L]  (hidden comment: CRCW0603732RFKEA)
R128  value 49.9k  [0603L]  (hidden comment: CRCW060349K9FKEA)
R130  value 732  [0603L]  (hidden comment: CRCW0603732RFKEA)
R131  value 100  [0603L]  (hidden comment: CRCW0603100RFKEA)
R132  value 8.2k  [0603L]  (hidden comment: RC0603JR-078K2L)
R133  value 10.2k  [0603L]  (hidden comment: CRCW060310K2FKEA)
R134  value 100  [0603L]  (hidden comment: CRCW0603100RFKEA)
R135  value 51k  [0603L]  (hidden comment: CRCW060351K0JNEA)
R136  value 10.7k  [0603L]  (hidden comment: CRCW060310K7FKEA)
R139  value 15.0k  [0603]  (hidden comment: RC0603FR-0715KL)
R140  value 3.01k  [0603]  (hidden comment: CRCW06033K01FKEA)
R161  value 560  [0603L]  (hidden comment: CRCW0603560RJNEA)
R162  value 560  [0603L]  (hidden comment: CRCW0603560RJNEA)
R181  value 560  [0603L]  (hidden comment: CRCW0603560RJNEA)
R182  value 560  [0603L]  (hidden comment: CRCW0603560RJNEA)
R183  value 10.0k  [0603L]  (hidden comment: CRCW060310K0FKEA)
R184  value 1.10k  [0603L]  (hidden comment: CRCW06031K10FKEA)
R185  value 10.0k  [0603L]  (hidden comment: CRCW060310K0FKEA)
R186  value 47k  [0603L]  (hidden comment: CRCW060347K0JNEA)
R199  value 49.9k  [0603L]  (hidden comment: CRCW060349K9FKEA)
R255  value 49.9k  [0603L]  (hidden comment: CRCW060349K9FKEA)
R256  value 49.9k  [0603L]  (hidden comment: CRCW060349K9FKEA)
R257  value 49.9k  [0603L]  (hidden comment: CRCW060349K9FKEA)
R259  value 1.00k  [0603L]  (hidden comment: CRCW06031K00FKEA)
R260  value 20.0k  [0603L]  (hidden comment: CRCW060320K0FKEA)
R261  value 100k  [0603L]  (hidden comment: CRCW0603100KFKEA)
R262  value 1.00k  [0603L]  (hidden comment: CRCW06031K00FKEA)
R263  value 20.0k  [0603L]  (hidden comment: CRCW060320K0FKEA)
R264  value 100k  [0603L]  (hidden comment: CRCW0603100KFKEA)
R265  value 20.0k  [0603L]  (hidden comment: CRCW060320K0FKEA)
R266  value 680k  [0603L]  (hidden comment: RC0603FR-07680KL)
R269  value 20.0k  [0603L]  (hidden comment: CRCW060320K0FKEA)
R270  value 680k  [0603L]  (hidden comment: RC0603FR-07680KL)
R272  value 39.0k  [0603L]  (hidden comment: RC0603FR-0739KL)
R273  value 100k  [0603L]  (hidden comment: CRCW0603100KFKEA)
R274  value 82.0k  [0603L]  (hidden comment: RC0603FR-0782KL)
R276  value 1.50k  [0603L]  (hidden comment: CRCW06031K50FKEA)
R278  value 20.0k  [0603L]  (hidden comment: CRCW060320K0FKEA)
RT1  value 100k ohm  [0603]  (hidden comment: NTCG164KF104F)
RT2  961102-6404-AR  [1X2 100MIL PITCH]  (value not drawn)
U15  UCLAMP0506A.TCT  [SC-89]
U16  LM431AIM3  [MF03A_L]
U18  EMB1433QSQ  [sqa48b]

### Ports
AUX (in), AUXTH (in), BAT14S, BAT[0..14], EN_CEXT_BYPASS (in), HEART (out)

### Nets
+3V3: C68.2 R24.2 R51.2 R115.1 R117.1 R119.1 R121.1 U18.3(VIO) U18.38(CHPnSD) U18.39(nRS) U18.40(nSD)
+5V_1: C71.1 R131.1 U18.28(VP)
+5VD: C72.1 D44.3(K) Q57.2(E) R274.1 R278.1 U18.35(CHPVP)
-5V1: C16.1 D49.1(A1) D49.2(A2) PING_OFF.2 Q56.2(E) R273.2 U16.3(A)
-5V2: C76.1 R134.1 U18.32(VM)
AGND: C71.2 C76.2 C192.2 U18.5(GND) U18.23(GND) U18.49(DAP)
BAT0: C68.1 C69.2 C72.2 C73.1 D49.3(K) NT6.2 PING_OUT1.1 Q49.2(E) R46.2 R113.2 R130.1 R185.2 R199.2 R255.2 R256.2 R257.2 U15.2 U18.4(DGND)  [also labelled GND]
RGND_BSP: C74.2 C75.2 C77.2 C78.2 C79.2 NT6.1 R128.1 R132.1 R135.1 R139.1 U18.31(GNDREF)
AUX_: C78.1 R128.2 RT1.2 RT2.1 U18.25(AUX) ; port AUX
AUXTH_: C79.1 R139.2 R140.1 U18.24(AUXTH) ; port AUXTH
BAT1: R124.1
BAT2: R123.1
BAT3: R122.1
BAT4: R120.1
BAT5: R118.1
BAT6: R116.1
BAT7: R114.1
BAT8: R112.1
BAT9: R111.1
BAT10: R110.1
BAT11: R109.1
BAT12: R108.1
BAT13: R107.1
BAT14: Q25.2(E) Q48.2(E) R89.2 R183.2
BAT14S_: R106.1 ; port BAT14S
C0: C189.2 C192.1 D55.2 D56.2 R130.2 U18.22(VSENSE_GND)
C1: C186.2 C189.1 R124.2 U18.21(VSENSE1)
C2: C184.2 C186.1 R123.2 U18.20(VSENSE2)
C3: C108.2 C184.1 R122.2 U18.19(VSENSE3)
C4: C108.1 C193.2 R120.2 U18.18(VSENSE4)
C5: C190.2 C193.1 R118.2 U18.17(VSENSE5)
C6: C187.2 C190.1 R116.2 U18.16(VSENSE6)
C7: C183.2 C187.1 R114.2 U18.15(VSENSE7)
C8: C109.2 C183.1 R112.2 U18.14(VSENSE8)
C9: C109.1 C194.2 R111.2 U18.13(VSENSE9)
C10: C191.2 C194.1 R110.2 U18.12(VSENSE10)
C11: C188.2 C191.1 R109.2 U18.11(VSENSE11)
C12: C185.2 C188.1 R108.2 U18.10(VSENSE12)
C13: C110.2 C185.1 R107.2 U18.9(VSENSE13)
C14: C110.1 D53.2 D54.2 R106.2 U18.8(VSENSE14)
DIN_LS: D54.1 Q25.3(C) Q54.3(C) R182.1
DOUT_LS: D56.1 Q53.2(E) R162.2 R263.1
EN_CEXT_BYPASS_: Q11.1(G) R24.1 ; port EN_CEXT_BYPASS
HEART_: R42.1 U18.2(HEART) ; port HEART
HTH: C77.1 R135.2 R136.1 U18.26(HTH)
LTH: C74.1 R132.2 R133.1 U18.27(LTH)
P_IN_1: D22.2(Anode) PING_IN1.1
P_IN_2: D18.2(Anode) PING_IN1.2
P_IN_3: PING_IN1.3 R55.1 U15.5
P_IN_4: PING_IN1.4 R51.1 U15.4
P_OUT_5: PING_OUT1.5 R45.2 U15.1
P_OUT_6: PING_OUT1.6 R43.2 U15.3
P_OUT_7: PING_OUT1.7 R42.2 U15.6
P_OUT_DOUT_LS: PING_OUT1.3 R262.2
P_OUT_PING_IO_LS: PING_OUT1.4 R259.2
PING_IO_LS: D55.1 Q52.2(S) R161.2 R261.1
PING_LS_IN: R43.1 R46.1 U18.47(PING_LS_IN)
PING_LS_OUT: R45.1 U18.48(PING_LS_OUT)
TOP_MOD_ID: R55.2 R113.1 R184.1 U18.45(TOP_MOD_ID)
VREF_OUT: R133.2 R136.2 R140.2 RT1.1 RT2.2 U18.30(VREFOUT)
NetC16_2: C16.2 D44.1(A1) D44.2(A2) PING_OFF.1 R278.2 U16.2(REF)
NetC69_1: C69.1 Q11.2(S)
NetC70_1: C70.1 U18.37(CHP)
NetC70_2: C70.2 U18.36(CHM)
NetC73_2: C73.2 R134.2 U18.33(CHPVM)
NetC75_1: C75.1 R131.2 U18.29(VPREF)
NetD15_1: D15.1(A1) R260.2
NetD15_2: D15.2(A2) R264.2
NetD15_3: D15.3(K) D24.3(K) Q56.3(C)
NetD18_1: D18.1(Cathode) R59.1
NetD22_1: D22.1(Cathode) R60.1
NetD24_1: D24.1(A1) R266.2
NetD24_2: D24.2(A2) R270.2
NetD53_1: D53.1 Q48.3(C) Q55.3(C) R181.2
NetQ11_3: Q11.3(D) U18.1(CXT)
NetQ25_1: Q25.1(B) Q48.1(B) R89.1 R183.1 R186.1
NetQ49_1: Q49.1(B) R184.2 R185.1
NetQ49_3: Q49.3(C) R186.2
NetQ52_1: Q52.1(G) R260.1 R261.2
NetQ52_3: Q52.3(D) R259.1
NetQ53_1: Q53.1(B) R263.2 R264.1
NetQ53_3: Q53.3(C) R262.1
NetQ54_1: Q54.1(B) R265.2 R266.1
NetQ54_2: Q54.2(E) R59.2 R265.1
NetQ55_1: Q55.1(B) R269.2 R270.1
NetQ55_2: Q55.2(E) R60.2 R269.1
NetQ56_1: Q56.1(B) R272.2 R273.1
NetQ57_1: Q57.1(B) R274.2 R276.1
NetQ57_3: Q57.3(C) R272.1
NetR115_2: R115.2 R199.1 U18.44(CELLN<3>)
NetR117_2: R117.2 R255.1 U18.43(CELLN<2>)
NetR119_2: R119.2 R256.1 U18.42(CELLN<1>)
NetR121_2: R121.2 R257.1 U18.41(CELLN<0>)
NetR161_1: R161.1 U18.46(PING_IO_LS)
NetR162_1: R162.1 U18.34(DOUT_LS)
NetR181_1: R181.1 U18.6(PING_IO_HS)
NetR182_2: R182.2 U18.7(DIN_LS)
NetR276_2: R276.2 U16.1(K)

Not connected (* = marked no-connect by the designer): PING_OUT1 2 8

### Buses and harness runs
bus BAT[0..14] = port BAT[0..14]

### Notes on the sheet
- CEXT_BYPASS
- circuit (and Q11)
- for test purpose
- THERMISTOR
- TI Information - Selective Disclosure

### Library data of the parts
C16 C68 C71 C72 C76 = C2012X7R1E105K: CAP, CERM, 1uF, 25V, +/-10%, X7R, 0805; Manufacturer: TDK; Cap_Case: 0805; ESR_Ohm: 0.0075; Polarized: N; TaMax_C: 125; TaMin_C: -55; Tolerance_%: 10; VDC_V: 25; Cap_F: 0.000001; CompType: Capacitor; Value1: 0.0075 ohm; U/M: EA; ValueDisplayed: 1µF
C69 C73-C75 C77-C79 = C1608X7R1C104K: as C22 on sheet uController
C70 = C1608X7R1H103K: CAP, CERM, 0.01uF, 50V, +/-10%, X7R, 0603; Manufacturer: TDK; Cap_Case: 0603; ESR_Ohm: 0.0539; Polarized: N; TaMax_C: 125; TaMin_C: -55; Tolerance_%: 10; VDC_V: 50; Cap_F: 0.00000001; CompType: Capacitor; Value1: 0.0539 ohm; U/M: EA; ValueDisplayed: 0.01µF
C108-C110 C183-C194 = C0603C225K9PACTU: CAP, CERM, 2.2uF, 6.3V, +/-10%, X5R, 0603; Manufacturer: Kemet; Cap_Case: 0603; Polarized: N; TaMax_C: 85; TaMin_C: -55; Tolerance_%: 10; VDC_V: 6.3; Cap_F: 0.0000022; CompType: Capacitor; U/M: EA
D15 D24 D44 D49 = MMBD1504A: Diode, Dual, 200V, 350mW, SOT-23; Manufacturer: Fairchild Semiconductor; CompType: Zener; Power_W: 0.350; Ct: 4pF; Value1: 0.350W; RJA_CperW: 556
D18 D22 = RS1M/B: 1A 1000V Recitfier; Manufacturer: Diodes Incorporated; CompType: Used in BOM report; SymbolVersion: 102209; SymbolCreator: cwiosc
D53-D56 = ESD5B5.0ST1G: TVS ESD BIDIRECT 5V SOD523; Manufacturer: ON Semiconductor; SymbolVersion: use current date i.e. 2008-05-20; SymbolCreator: Use LDAP id
NT6 = NetTie: Value1: DNP
PING_IN1 = 1565749-1: Tyco 025 Series Multi-Lock Connector 4 position
PING_OFF RT2 = 961102-6404-AR: CONN 1X2 HEADER 100mil pitch; Manufacturer: 3M; CompType: Connector; I max: 2A
PING_OUT1 = 1376350-2: Tyco 025 Series Multi-Lock Connector 8 position
Q11 = 2N7002W-7-F: as Q45 on sheet Communications
Q25 Q48 = BC856B-7-F, Diodes Inc.: Transistor, PNP, 65V, 0.1A, SOT-23; CompType: BJT; PNP: 1; NPN: 0; Vcesat1_V: 0.075; Value: 0.075V; IcRated_A: 0.1; HfeMax: 330
Q49 = BC846BLT1G, ON Semiconductor: Transistor, NPN, 65V, 0.1A, SOT-23; CompType: BJT; PNP: 0; NPN: 1; Vcesat1_V: 0.7; Value: 0.7V; IcRated_A: 0.1; HfeMax: 450; U/M: EA
Q52 = SI2337DS-T1-E3: MOSFET, P-CH, -80V, -1.2A, SOT-23; Manufacturer: Vishay-Siliconix; U/M: EA; ChType: P; VdsMax_V: -80; Value1: ? ohm; Value2: 11 nC; QgTyp_nC: 11; Vgs_V: -20; IdsMax_A: -1.2
Q53-Q55 Q57 = FMMT596TA: PNP, 1.4A, 100V; Manufacturer: Diodes Inc; CompType: BJT; IcRated_A: 0.3; Vceo_V: 200; Vcesat1_V: 0.2; Value: 0.2V; PNP: 1; NPN: 0; Value1: 0.3A
Q56 = FMMT495TA: NPN, 1A, 150V; Manufacturer: Diodes Inc.; CompType: BJT; IcRated_A: 1; Vceo_V: 150; Vcesat1_V: 0.2; Value: 0.2V; PNP: 0
R24 R113 R115 R117 R119 R121 R128 R199 R255-R257 = CRCW060349k9FKEA: RES, 49.9k ohm, 1%, 0.1W, 0603; Manufacturer: Vishay-Dale; CompType: Resistor; Tolerance_%: 1; VDC_V: 75; Power_W: 0.1; Res_Ohm: 49900; Value_Code: 49k9; EIA_Code: E96; TempCo: 100 ppm/C; U/M: EA
R42 R43 R45 R55 = RC0603FR-0710RL: RES, 10.0 ohm, 1%, 0.1W, 0603; Manufacturer: Yageo America; CompType: Resistor; Tolerance_%: 1; VDC_V: 150; Power_W: 0.1; Res_Ohm: 10; Value_Code: 10R0; EIA_Code: E96; TempCo: 200 ppm/C; U/M: EA
R46 R186 = CRCW060347K0JNEA: RES, 47k ohm, 5%, 0.1W, 0603; Manufacturer: Vishay-Dale; CompType: Resistor; Tolerance_%: 5; VDC_V: 75; Power_W: 0.1; Res_Ohm: 47000; Value_Code: 47k0; EIA_Code: E24; TempCo: 200 ppm/C; U/M: EA
R51 = CRCW06031K00FKEA: as R47 on sheet uController
R59 R60 R259 R262 = CRCW06031K00FKEA: RES, 1.00k ohm, 1%, 0.1W, 0603; Manufacturer: Vishay-Dale; CompType: Resistor; Tolerance_%: 1; VDC_V: 75; Power_W: 0.1; Res_ohm: 1000; Value_Code: 1k00; EIA_Code: E96; U/M: EA; TempCo: 100 ppm/C
R89 R183 R185 = CRCW060310K0FKEA: as R151 on sheet Communications
R106-R112 R114 R116 R118 R120 R122-R124 R130 = CRCW0603732RFKEA: RES, 732 ohm, 1%, 0.1W, 0603; Manufacturer: Vishay-Dale; CompType: Resistor; Tolerance_%: 1; VDC_V: 75; Power_W: 0.1; Value_Code: 732R; EIA_Code: E96; U/M: EA; TempCo: 100 ppm/C
R131 R134 = CRCW0603100RFKEA: RES, 100 ohm, 1%, 0.1W, 0603; Manufacturer: Vishay-Dale; CompType: Resistor; Tolerance_%: 1; VDC_V: 75; Power_W: 0.1; Value_Code: 100R; EIA_Code: E96; TempCo: 100 ppm/C; U/M: EA
R132 = RC0603JR-078K2L: RES, 8.2k ohm, 5%, 0.1W, 0603; Manufacturer: Yageo America; CompType: Resistor; Tolerance_%: 5; VDC_V: 50; Power_W: 0.1; Res_Ohm: 8200; Value_Code: 8k20; EIA_Code: E24; TempCo: 100 ppm/C; U/M: EA
R133 = CRCW060310K2FKEA: RES, 10.2k ohm, 1%, 0.1W, 0603; Manufacturer: Vishay-Dale; CompType: Resistor; Tolerance_%: 1; VDC_V: 75; Power_W: 0.1; Res_Ohm: 10200; Value_Code: 10k2; EIA_Code: E96; TempCo: 100 ppm/C; U/M: EA
R135 = CRCW060351K0JNEA: RES, 51k ohm, 5%, 0.1W, 0603; Manufacturer: Vishay-Dale; CompType: Resistor; Tolerance_%: 5; VDC_V: 75; Power_W: 0.1; Res_Ohm: 51000; Value_Code: 51k0; EIA_Code: E24; TempCo: 200 ppm/C; U/M: EA
R136 = CRCW060310K7FKEA: RES, 10.7k ohm, 1%, 0.1W, 0603; Manufacturer: Vishay-Dale; CompType: Resistor; Tolerance_%: 1; VDC_V: 75; Power_W: 0.1; Res_Ohm: 10700; Value_Code: 10k7; EIA_Code: E96; TempCo: 100 ppm/C; U/M: EA
R139 = RC0603FR-0715KL: RES, 15.0k ohm, 1%, 0.1W, 0603; Manufacturer: Yageo America; CompType: Resistor; Res_ohm: 15000; Value_Code: 15k0; Tolerance_%: 1; Power_W: 0.1; VDC_V: 150; TempCo: 200 ppm/C; EIA_Code: E96; U/M: EA
R140 = CRCW06033K01FKEA: RES, 3.01k ohm, 1%, 0.1W, 0603; Manufacturer: Vishay-Dale; CompType: Resistor; Res_ohm: 3010; Value_Code: 3k01; Tolerance_%: 1; Power_W: 0.1; VDC_V: 75; TempCo: 100 ppm/C; EIA_Code: E96; U/M: EA
R161 R162 R181 R182 = CRCW0603560RJNEA: RES, 560 ohm, 5%, 0.1W, 0603; Manufacturer: Vishay-Dale; CompType: Resistor; Tolerance_%: 5; VDC_V: 75; Power_W: 0.1; Value_Code: 560R; EIA_Code: E24; TempCo: 200 ppm/C; U/M: EA
R184 = CRCW06031K10FKEA: RES, 1.10k ohm, 1%, 0.1W, 0603; Manufacturer: Vishay-Dale; CompType: Resistor; Tolerance_%: 1; VDC_V: 75; Power_W: 0.1; Res_Ohm: 1100; Value_Code: 1k10; EIA_Code: E96; TempCo: 100 ppm/C; U/M: EA
R260 R263 R265 R269 R278 = CRCW060320K0FKEA: RES, 20.0k ohm, 1%, 0.1W, 0603; Manufacturer: Vishay-Dale; CompType: Resistor; Tolerance_%: 1; VDC_V: 75; Power_W: 0.1; Res_ohm: 20000; Value_Code: 20k0; EIA_Code: E96; U/M: EA; TempCo: 100 ppm/C
R261 R264 R273 = CRCW0603100KFKEA: RES, 100k ohm, 1%, 0.1W, 0603; Manufacturer: Vishay-Dale; CompType: Resistor; Tolerance_%: 1; VDC_V: 75; Power_W: 0.1; Res_ohm: 100000; EIA_Code: E96; U/M: EA; TempCo: 100 ppm/C
R266 R270 = RC0603FR-07680KL: RES, 680k ohm, 1%, 0.1W, 0603; Manufacturer: Yageo America; CompType: Resistor; Tolerance_%: 1; VDC_V: 150; Power_W: 0.1; Res_ohm: 680000; U/M: EA; TempCo: 200 ppm/C
R272 = RC0603FR-0739KL: RES, 39.0k ohm, 1%, 0.1W, 0603; Manufacturer: Yageo America; CompType: Resistor; Tolerance_%: 1; VDC_V: 150; Power_W: 0.1; Res_ohm: 39000; Value_Code: 39k0; U/M: EA; TempCo: 200 ppm/C
R274 = RC0603FR-0782KL: RES, 82.0k ohm, 1%, 0.1W, 0603; Manufacturer: Yageo America; CompType: Resistor; Tolerance_%: 1; VDC_V: 150; Power_W: 0.1; Res_ohm: 82000; Value_Code: 82k0; U/M: EA; TempCo: 200 ppm/C
R276 = CRCW06031K50FKEA: RES, 1.50k ohm, 1%, 0.1W, 0603; Manufacturer: Vishay-Dale; CompType: Resistor; Tolerance_%: 1; VDC_V: 75; Power_W: 0.1; Res_ohm: 1500; Value_Code: 1k50; EIA_Code: E96; U/M: EA; TempCo: 100 ppm/C
RT1 = NTCG164KF104F: Thermistor NTC, 100k ohm, 1%, 0603; Manufacturer: TDK; Tolerance_%: 1; TaMin_C: -40; TaMax_C: 125; U/M: EA
U15 = UCLAMP0506A.TCT: TVS ESD BIDIRECT 5V SOT-666; Manufacturer: SemTech; SymbolVersion: use current date i.e. 2008-05-20; SymbolCreator: CSXHSC
U16 = LM431AIM3: Adjustable Precision Zener Shunt Regulator, 3-pin SOT-23; Manufacturer: National Semiconductor; CompType: MiscPower; PackageTopMarking: N1E*XTT; PowerWise: N
U18 = EMB1433QSQ: Battery Stack Protection WCOMP; Manufacturer: National Semiconductor; CompType: Used in BOM report; SymbolVersion: 100509; SymbolCreator: cwiosc

## Sheet TS.SchDoc: Temp Sense
size B; Date: Not shown in title block; ApprovedBy: Not shown in title block; CheckedBy: Not shown in title block; Author: Not shown in title block; CompanyName: Not shown in title block; DrawnBy: Francis Houde; Engineer: Francis House; Organization: SEMS; Address1: Not shown in title block; Address2: Not shown in title block; Address3: Not shown in title block; Address4: Not shown in title block; DocumentNumber: 13; SheetNumber: 12; SheetTotal: 14; PageSetup: Record=PageOptions|CenterHorizontal=True|CenterVertical=True|PrintScale=0.70|XCorrection=1.00|YCorrection=1.00|PrintKind=0|BorderSize=5000000|LeftOffset=0|BottomOffset=0|Orientation=2|PaperLength=1000|PaperWidth=1000|Scale=100|PaperSource=15|PrintQuality=600|MediaType=1|DitherType=10|PaperKind=Letter|PrintScaleMode=1
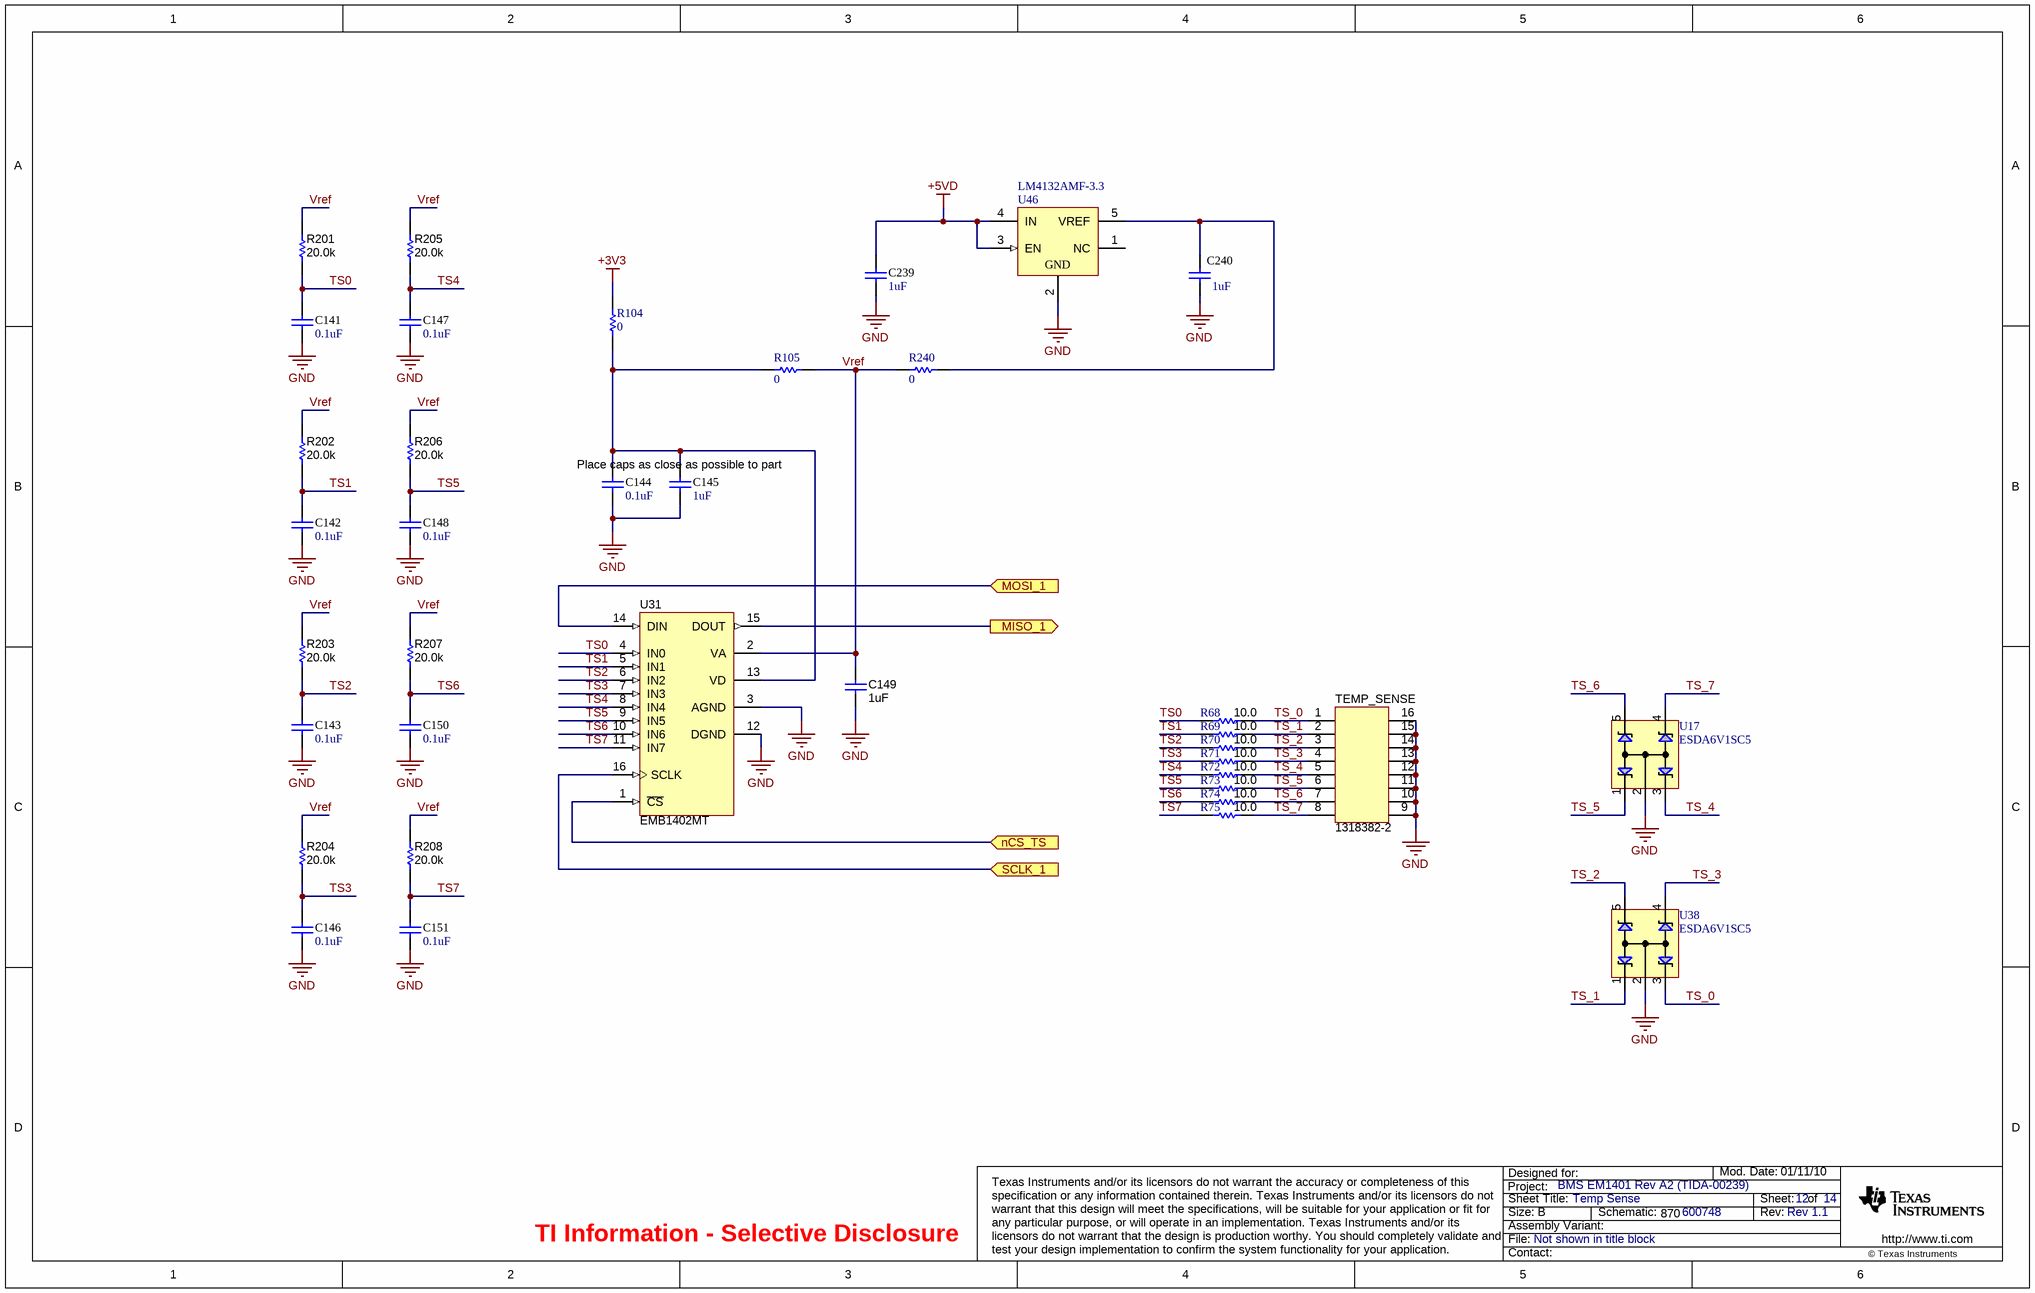
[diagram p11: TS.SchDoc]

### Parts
C141  value 0.1uF  [0603L]  (hidden comment: C1608X7R1E104K)
C142  value 0.1uF  [0603L]  (hidden comment: C1608X7R1E104K)
C143  value 0.1uF  [0603L]  (hidden comment: C1608X7R1E104K)
C144  value 0.1uF  [0603L]  (hidden comment: C1608X7R1E104K)
C145  value 1uF  [0805_HV]  (hidden comment: C0805C105K4RACTU)
C146  value 0.1uF  [0603L]  (hidden comment: C1608X7R1E104K)
C147  value 0.1uF  [0603L]  (hidden comment: C1608X7R1E104K)
C148  value 0.1uF  [0603L]  (hidden comment: C1608X7R1E104K)
C149  value 1uF  [0603L]  (hidden comment: C1608X5R1A105K)
C150  value 0.1uF  [0603L]  (hidden comment: C1608X7R1E104K)
C151  value 0.1uF  [0603L]  (hidden comment: C1608X7R1E104K)
C239  value 1uF  [0603L]  (hidden comment: C1608X5R1C105K)
C240  value 1uF  [0603L]  (hidden comment: C1608X5R1C105K)
R68  value 10.0  [0603L]  (hidden comment: RC0603FR-0710RL)
R69  value 10.0  [0603L]  (hidden comment: RC0603FR-0710RL)
R70  value 10.0  [0603L]  (hidden comment: RC0603FR-0710RL)
R71  value 10.0  [0603L]  (hidden comment: RC0603FR-0710RL)
R72  value 10.0  [0603L]  (hidden comment: RC0603FR-0710RL)
R73  value 10.0  [0603L]  (hidden comment: RC0603FR-0710RL)
R74  value 10.0  [0603L]  (hidden comment: RC0603FR-0710RL)
R75  value 10.0  [0603L]  (hidden comment: RC0603FR-0710RL)
R104  value 0  [0603L]  (hidden comment: CRCW06030000Z0EA)
R105  value 0  [0603L]  (hidden comment: CRCW06030000Z0EA)
R201  value 20.0k  [0603L]  (hidden comment: CRCW060320K0FKEA)
R202  value 20.0k  [0603L]  (hidden comment: CRCW060320K0FKEA)
R203  value 20.0k  [0603L]  (hidden comment: CRCW060320K0FKEA)
R204  value 20.0k  [0603L]  (hidden comment: CRCW060320K0FKEA)
R205  value 20.0k  [0603L]  (hidden comment: CRCW060320K0FKEA)
R206  value 20.0k  [0603L]  (hidden comment: CRCW060320K0FKEA)
R207  value 20.0k  [0603L]  (hidden comment: CRCW060320K0FKEA)
R208  value 20.0k  [0603L]  (hidden comment: CRCW060320K0FKEA)
R240  value 0  [0603L]  (hidden comment: CRCW06030000Z0EA)
TEMP_SENSE  1318382-2  [1318382-2]
U17  ESDA6V1SC5  [MF05A_M]
U31  EMB1402MT  [MTC16_N]
U38  ESDA6V1SC5  [MF05A_M]
U46  LM4132AMF-3.3  [MF05A_N]

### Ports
MISO_1 (out, see 1[1C]), MOSI_1 (in, see 1[1C]), nCS_TS (in, see 1[1C]), SCLK_1 (in, see 1[1C])

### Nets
+3V3: R104.1
+5VD: C239.1 U46.3(EN) U46.4(IN)
GND: C141.2 C142.2 C143.2 C144.2 C145.2 C146.2 C147.2 C148.2 C149.2 C150.2 C151.2 C239.2 C240.2 TEMP_SENSE.9 TEMP_SENSE.10 TEMP_SENSE.11 TEMP_SENSE.12 TEMP_SENSE.13 TEMP_SENSE.14 TEMP_SENSE.15 TEMP_SENSE.16 U17.2(IO2) U31.3(AGND) U31.12(DGND) U38.2(IO2) U46.2(GND)  [project net BAT0]
MISO_1_: U31.15(DOUT) ; port MISO_1
MOSI_1_: U31.14(DIN) ; port MOSI_1
nCS_TS_: U31.1(~{CS}) ; port nCS_TS
SCLK_1_: U31.16(SCLK) ; port SCLK_1
TS0: C141.1 R68.1 R201.1 U31.4(IN0)
TS1: C142.1 R69.1 R202.1 U31.5(IN1)
TS2: C143.1 R70.1 R203.1 U31.6(IN2)
TS3: C146.1 R71.1 R204.1 U31.7(IN3)
TS4: C147.1 R72.1 R205.1 U31.8(IN4)
TS5: C148.1 R73.1 R206.1 U31.9(IN5)
TS6: C150.1 R74.1 R207.1 U31.10(IN6)
TS7: C151.1 R75.1 R208.1 U31.11(IN7)
TS_0: R68.2 TEMP_SENSE.1 U38.3(IO3)
TS_1: R69.2 TEMP_SENSE.2 U38.1(IO1)
TS_2: R70.2 TEMP_SENSE.3 U38.5(IO5)
TS_3: R71.2 TEMP_SENSE.4 U38.4(IO4)
TS_4: R72.2 TEMP_SENSE.5 U17.3(IO3)
TS_5: R73.2 TEMP_SENSE.6 U17.1(IO1)
TS_6: R74.2 TEMP_SENSE.7 U17.5(IO5)
TS_7: R75.2 TEMP_SENSE.8 U17.4(IO4)
Vref: C149.1 R105.2 R201.2 R202.2 R203.2 R204.2 R205.2 R206.2 R207.2 R208.2 R240.1 U31.2(VA)
NetC144_1: C144.1 C145.1 R104.2 R105.1 U31.13(VD)
NetC240_1: C240.1 R240.2 U46.5(VREF)

Not connected (* = marked no-connect by the designer): U46 1(NC)

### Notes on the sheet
- Place caps as close as possible to part
- TI Information - Selective Disclosure

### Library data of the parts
C141-C144 C146-C148 C150 C151 = C1608X7R1E104K: CAP, CERM, 0.1uF, 25V, +/-10%, X7R, 0603; Manufacturer: TDK; Cap_Case: 0603; ESR_Ohm: 0.017; Polarized: N; TaMax_C: 125; TaMin_C: -55; Tolerance_%: 10; VDC_V: 25; Cap_F: 0.0000001; CompType: Capacitor; Value1: 0.017 ohm; U/M: EA; ValueDisplayed: 0.1µF
C145 = C0805C105K4RACTU: CAP, CERM, 1uF, 16V, +/-10%, X7R, 0805; Manufacturer: Kemet; Cap_Case: 0805; ESR_Ohm: 0.015; IRMS_A: 8.19; Polarized: N; TaMax_C: 125; TaMin_C: -55; Tolerance_%: 10; VDC_V: 16; Cap_F: 0.000001; CompType: Capacitor; Value1: 0.015 ohm; U/M: EA; ValueDisplayed: 1µF
C149 = C1608X5R1A105K: CAP, CERM, 1uF, 10V, +/-10%, X5R, 0603; Manufacturer: TDK; Cap_Case: 0603; ESR_Ohm: 0.0057; Polarized: N; TaMax_C: 85; TaMin_C: -55; Tolerance_%: 10; Cap_F: 0.000001; CompType: Capacitor; Value1: 0.0057 ohm; U/M: EA; ValueDisplayed: 1µF
C239 C240 = C1608X5R1C105K: CAP, CERM, 1uF, 16V, +/-10%, X5R, 0603; Manufacturer: TDK; Cap_Case: 0603; ESR_Ohm: 0.0057; Polarized: N; TaMax_C: 85; TaMin_C: -55; Tolerance_%: 10; VDC_V: 16; Cap_F: 0.000001; CompType: Capacitor; Value1: 0.0057 ohm; U/M: EA; ValueDisplayed: 1µF
R68-R75 = RC0603FR-0710RL: as R42 on sheet Battery Stack Protection
R104 R105 R240 = CRCW06030000Z0EA: as R56 on sheet uController
R201-R208 = CRCW060320K0FKEA: as R260 on sheet Battery Stack Protection
TEMP_SENSE = 1318382-2: Tyco 025 Series Multi-Lock Connector 16 position
U17 U38 = ESDA6V1SC5: DIODE ARRAY ESD 6.1V Breakdown; Manufacturer: STMicroelectronics; CompType: ESD protection
U31 = EMB1402MT: 8-Channel, 500 kSPS to 1 MSPS, 12-Bit A/D Converter; Manufacturer: National Semiconductor; CompType: ADC IC; PowerWise: Y
U46 = LM4132AMF-3.3: Precision Low Dropout Voltage Reference, 5-pin SOT-23; Manufacturer: National Semiconductor; CompType: Voltage Reference IC; PackageTopMarking: R4EA*XTT; PowerWise: N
